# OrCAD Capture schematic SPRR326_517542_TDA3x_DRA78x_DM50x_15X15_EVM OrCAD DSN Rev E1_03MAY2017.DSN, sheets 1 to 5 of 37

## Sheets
1 SH01 - TITLE PAGE: title: TDA3x/DRA78x/DM50x - 15X15 EVM; rev: E1; company: TEXAS INSTRUMENTS INCORPORATED; note: 517542; note: TI CONFIDENTIAL - NDA RESTRICTIONS; note: Preliminary Information - Subject to change
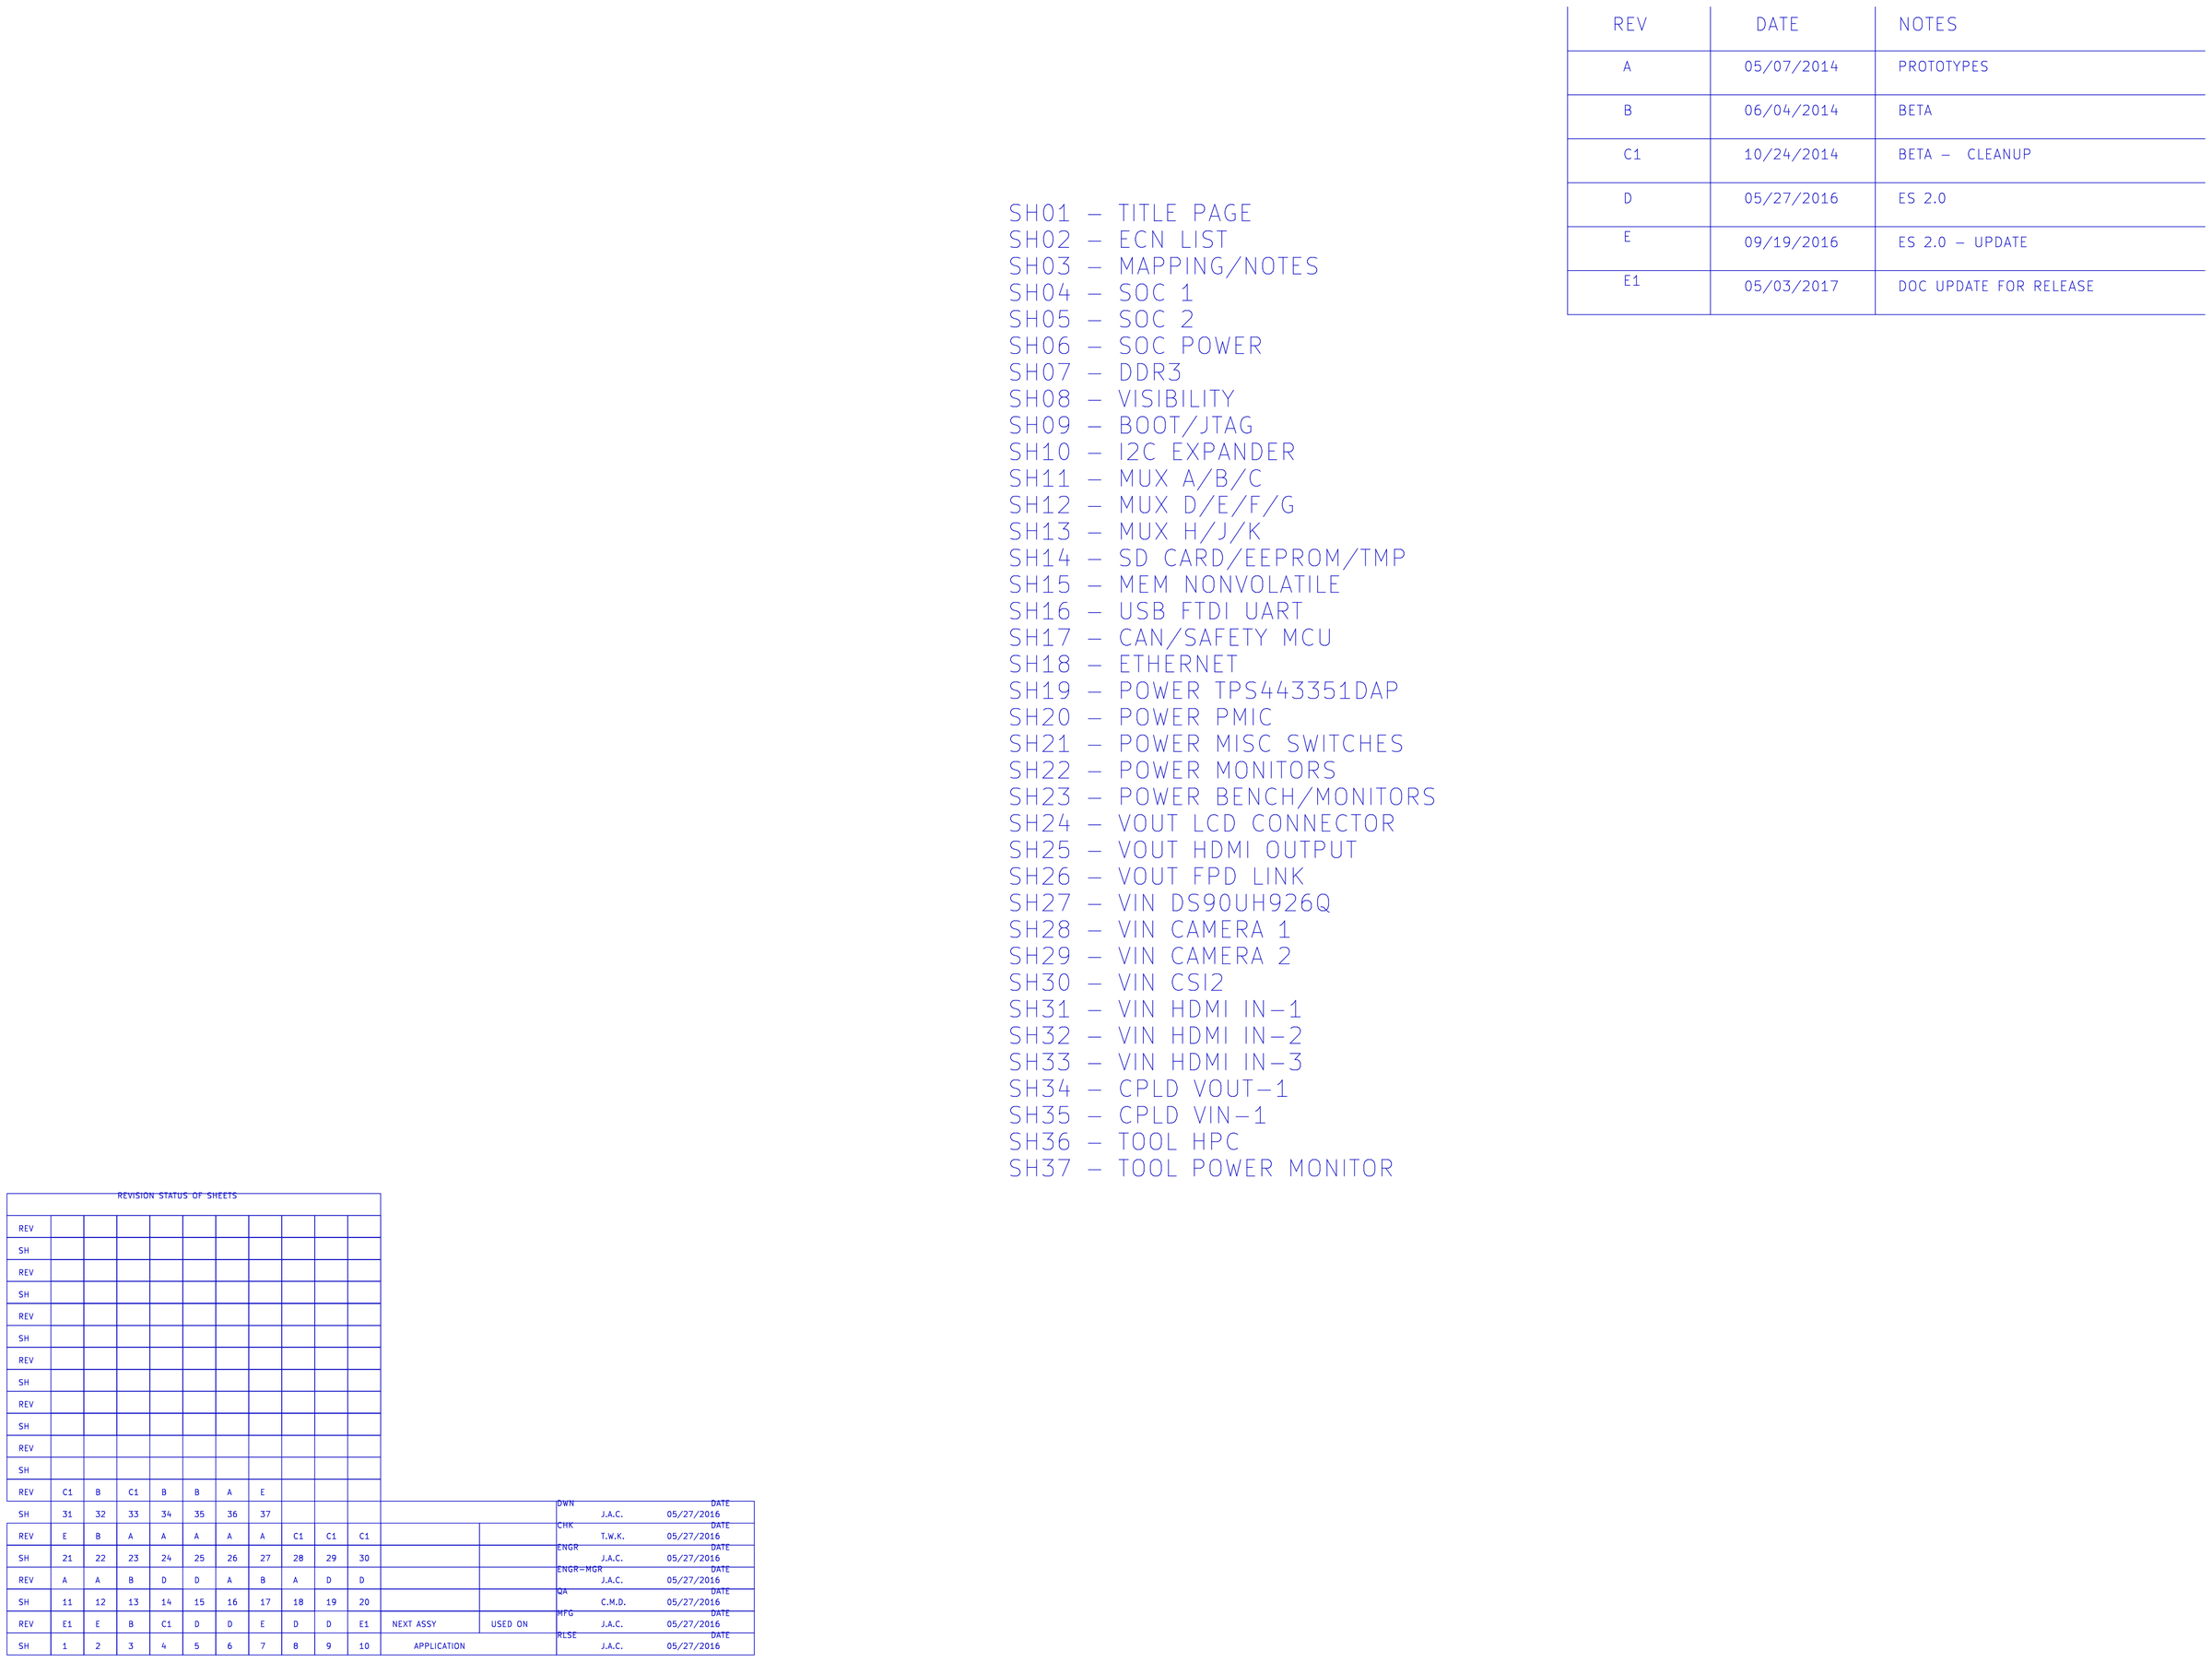
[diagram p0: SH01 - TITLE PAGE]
2 SH02 - ECN LIST: rev: E
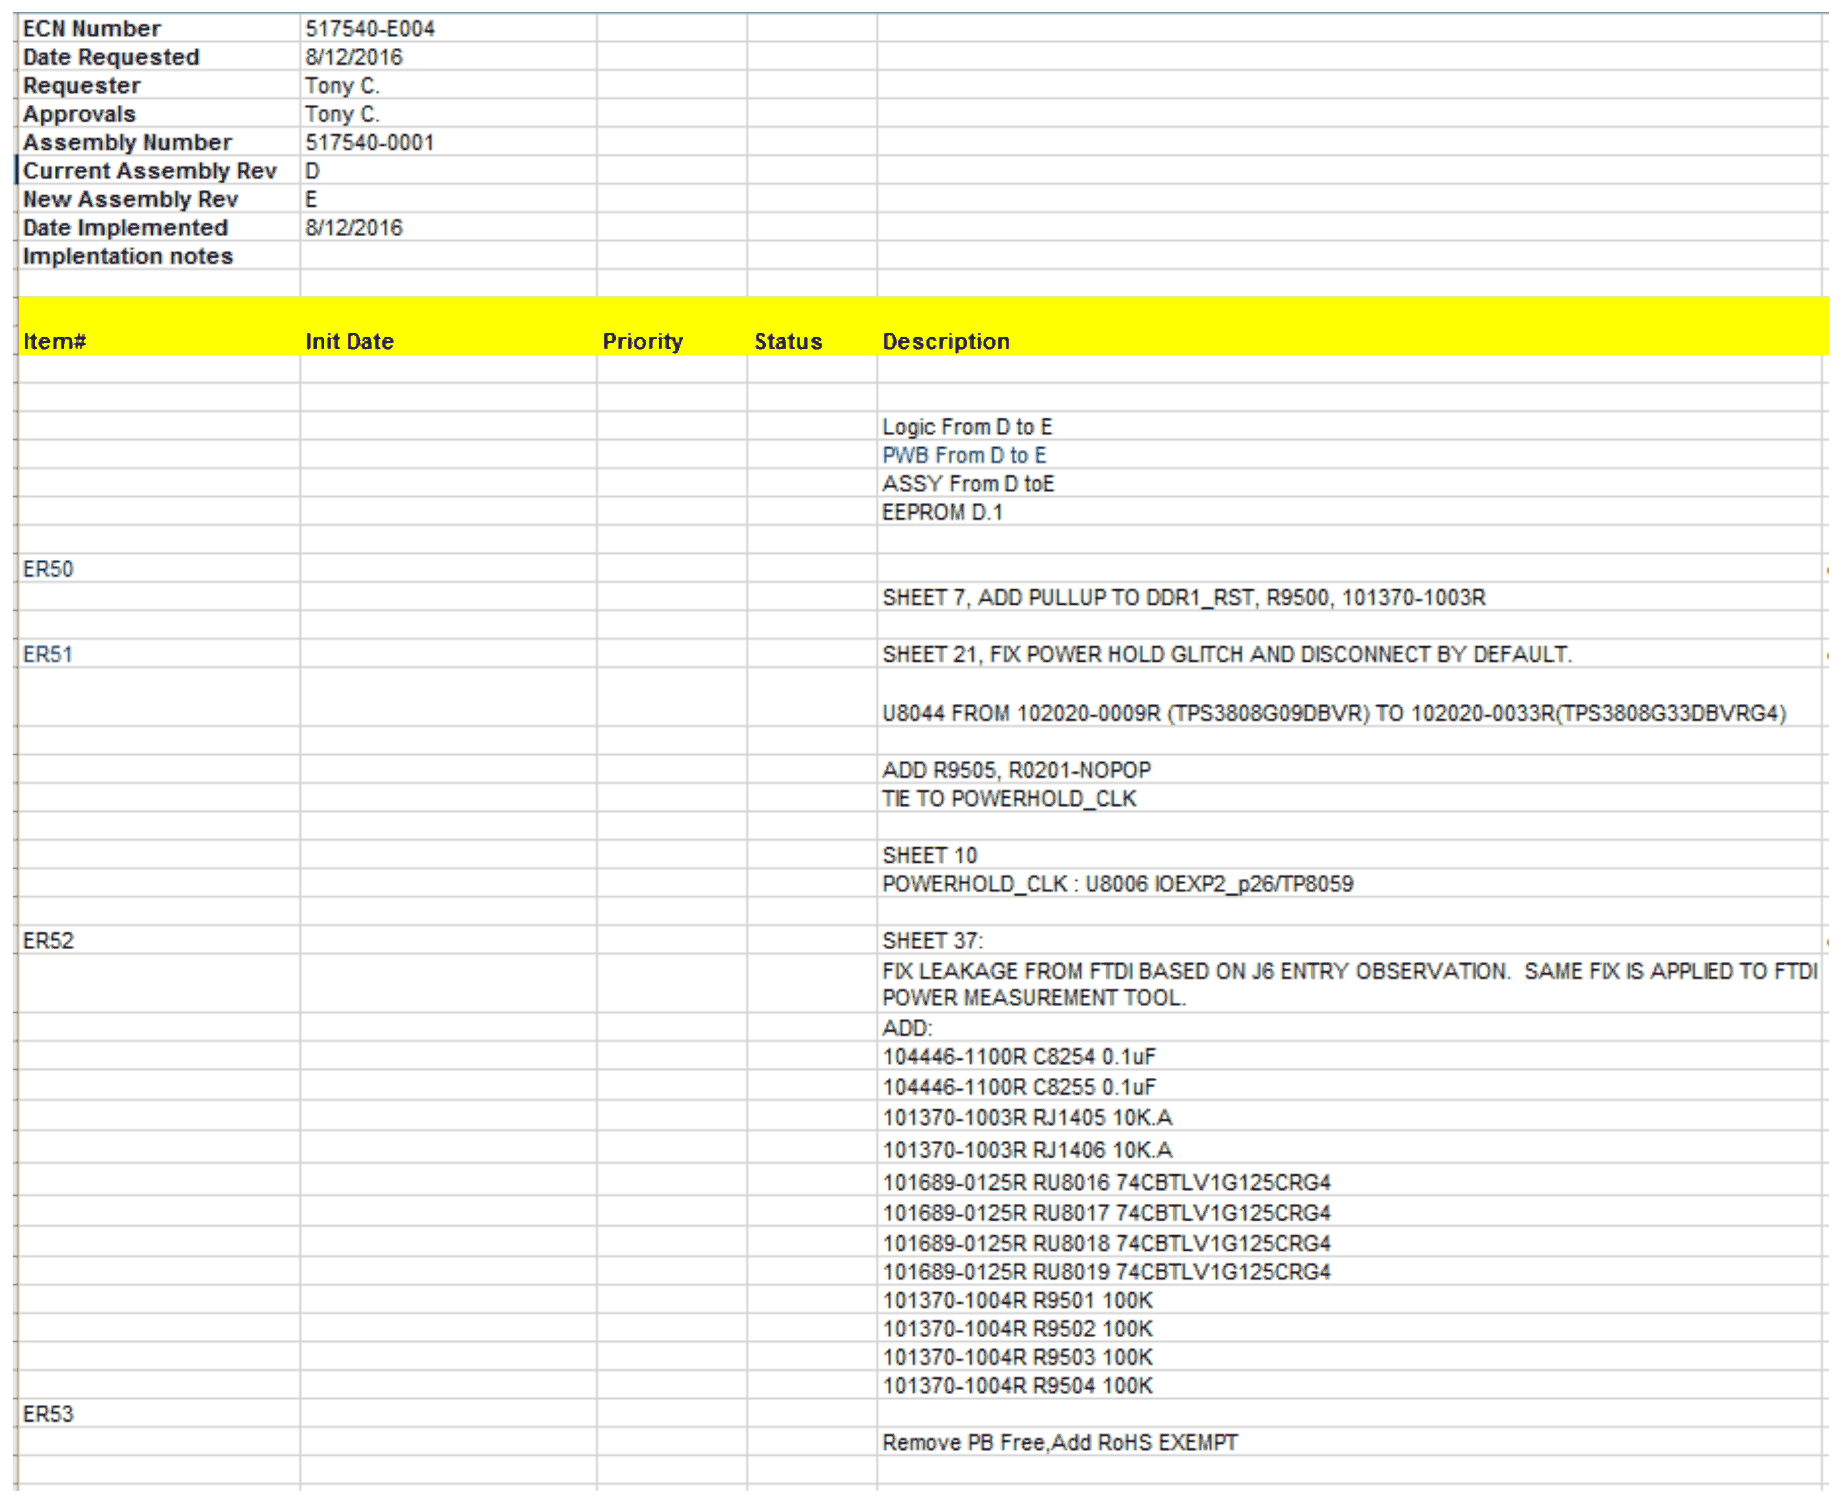
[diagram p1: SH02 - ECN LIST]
3 SH04 - SOC 1: size C; rev: C1
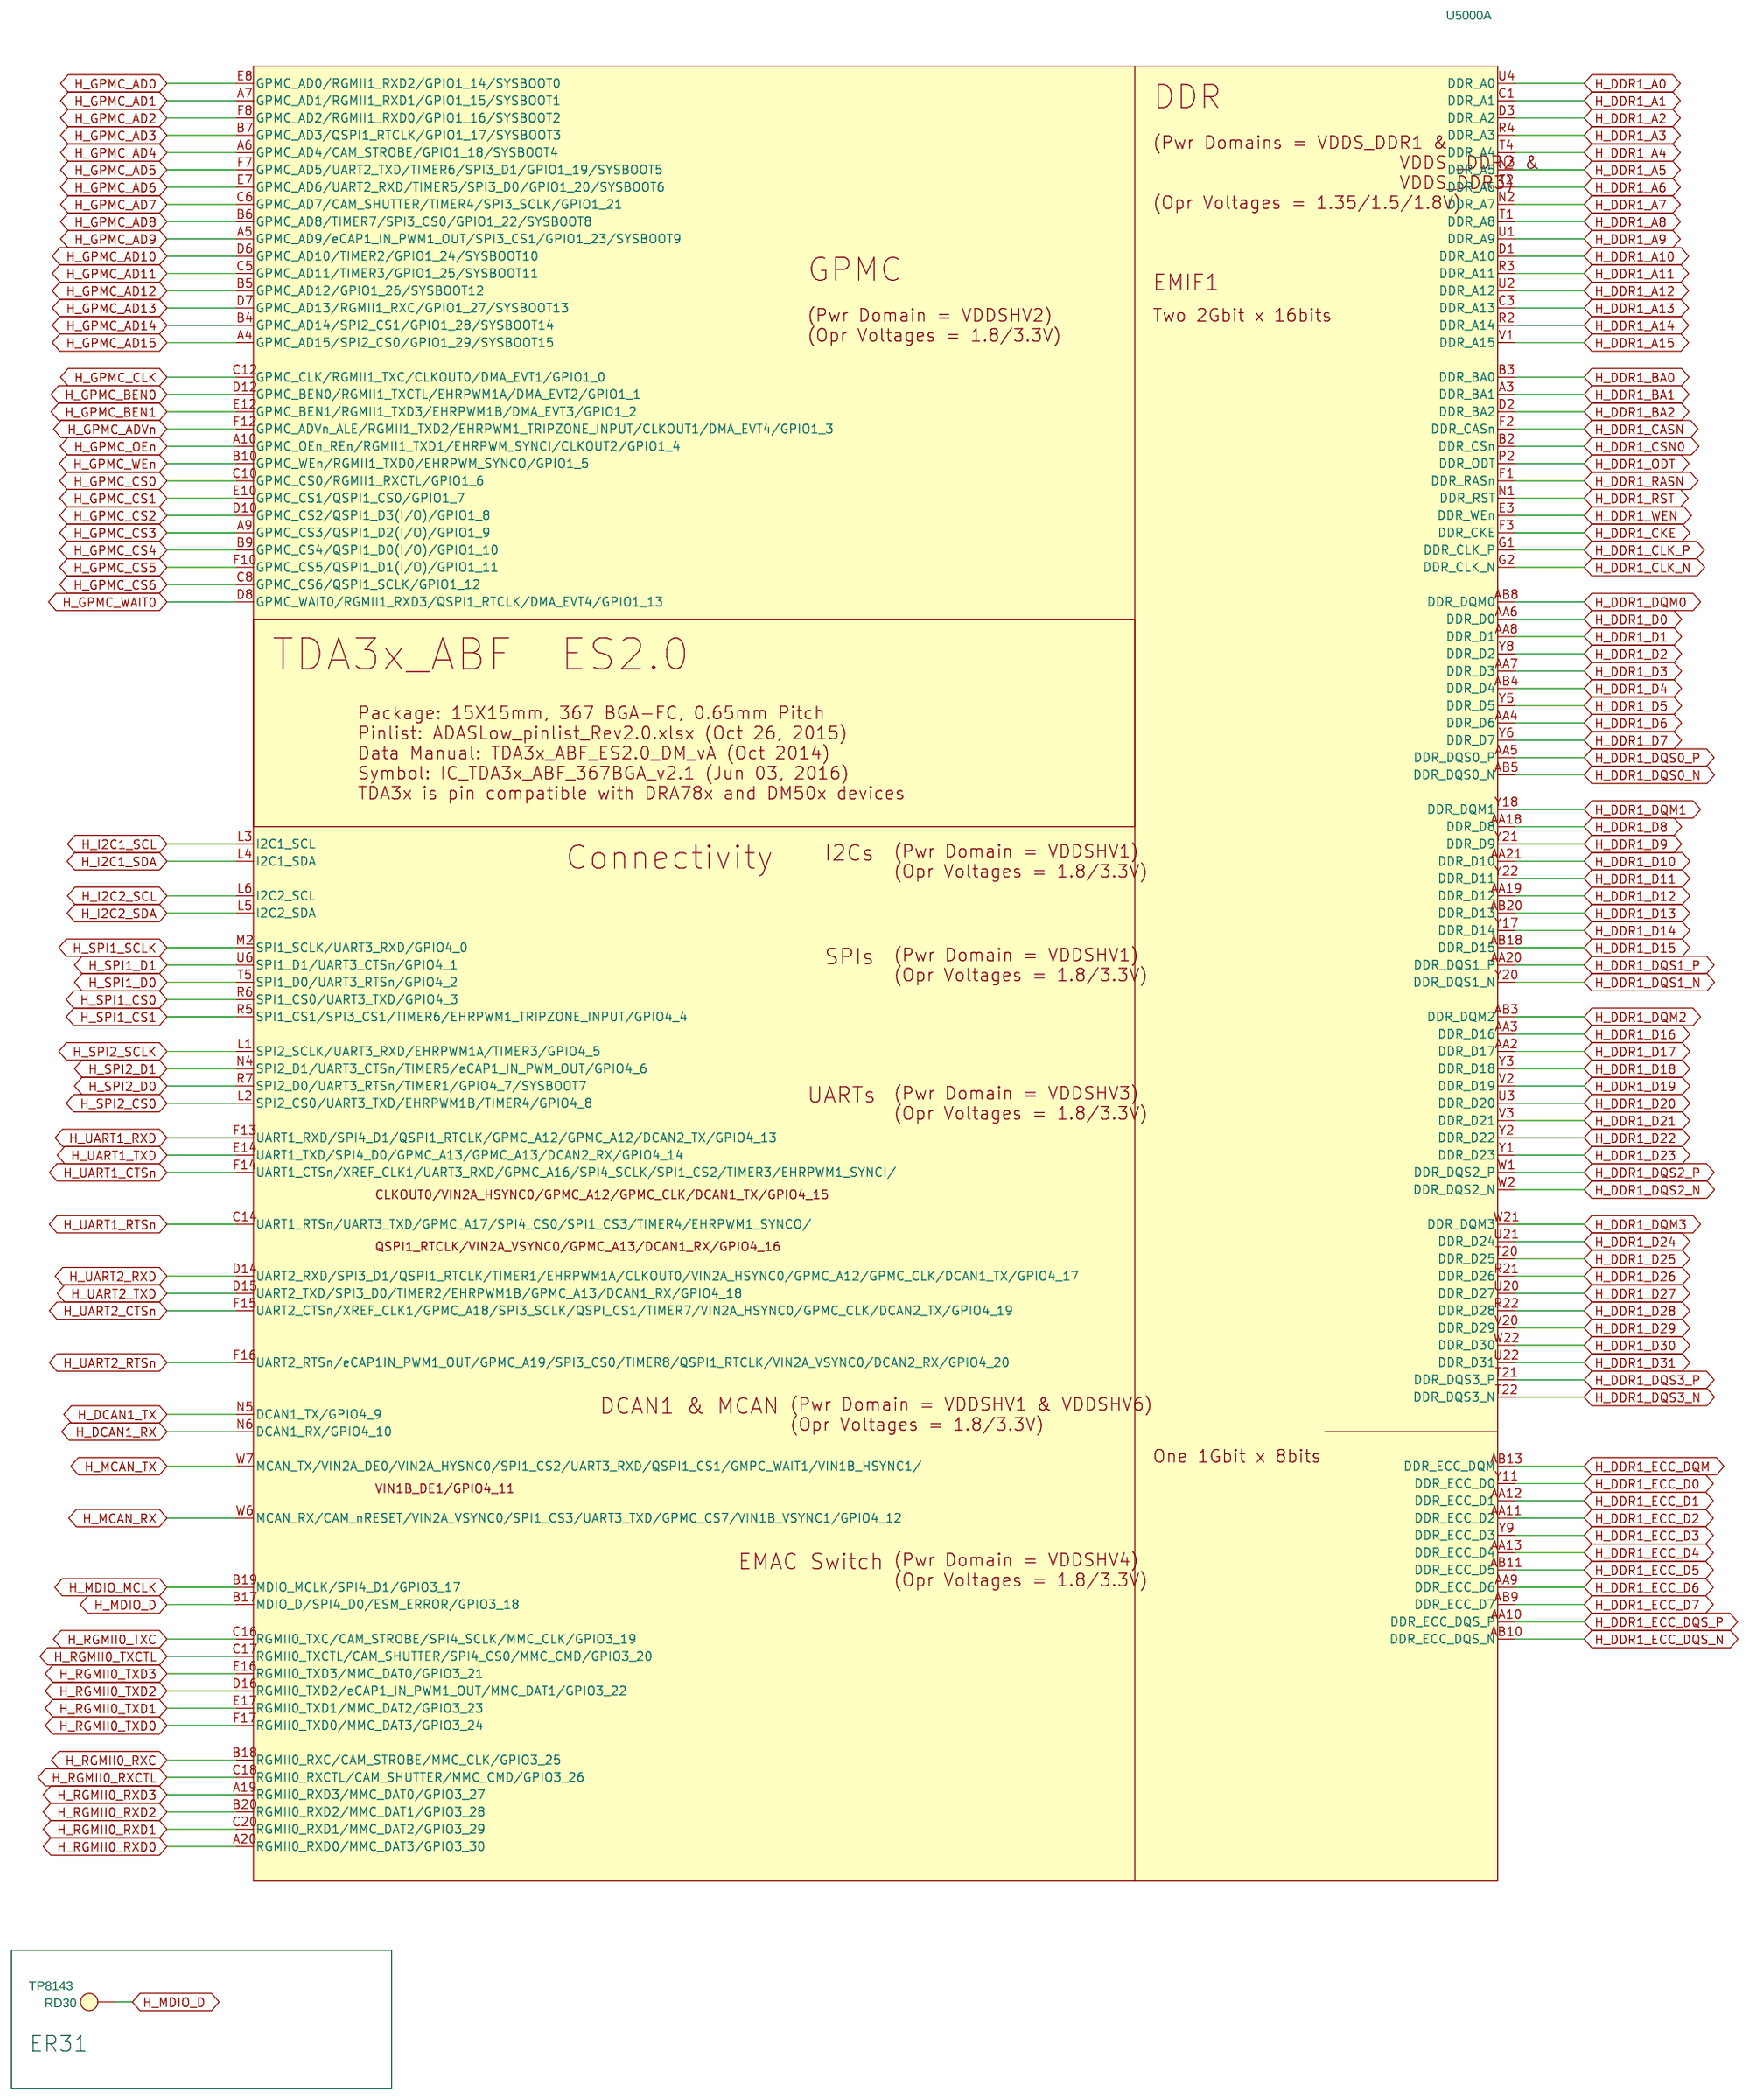
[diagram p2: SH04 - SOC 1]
4 SH05 - SOC 2: size C; rev: D
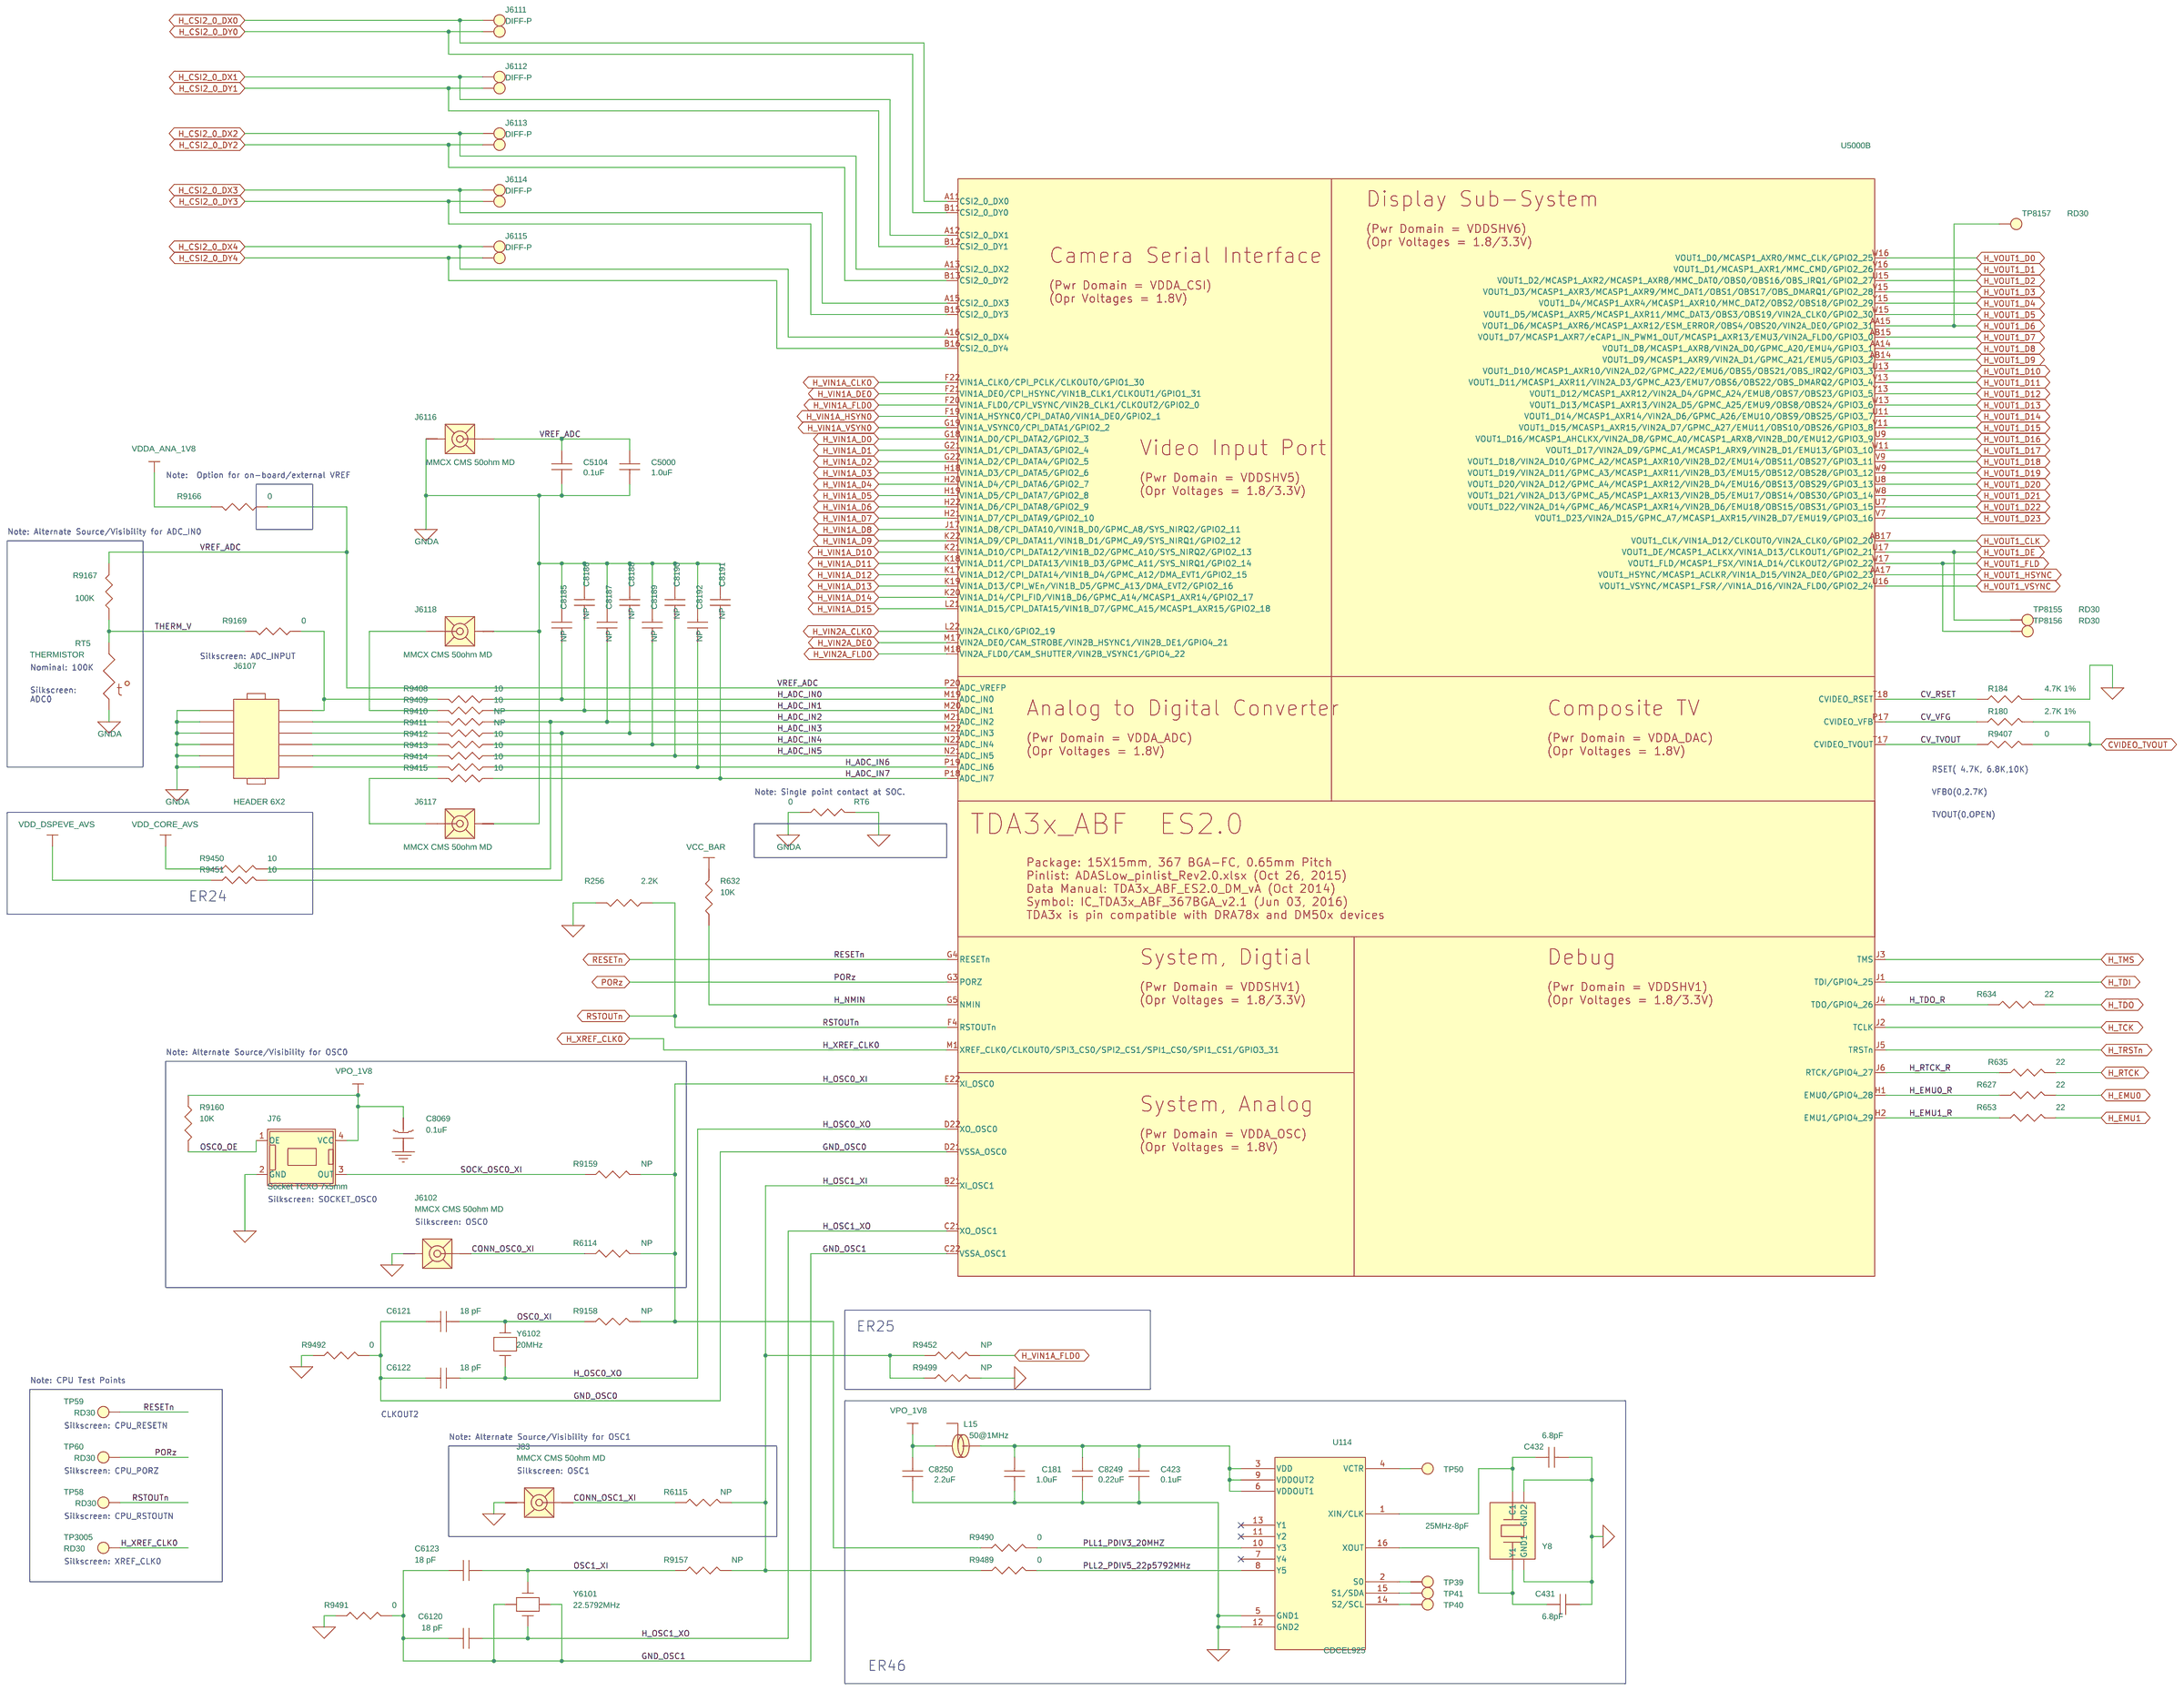
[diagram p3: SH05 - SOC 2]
5 SH06 - SOC POWER: size C; rev: D
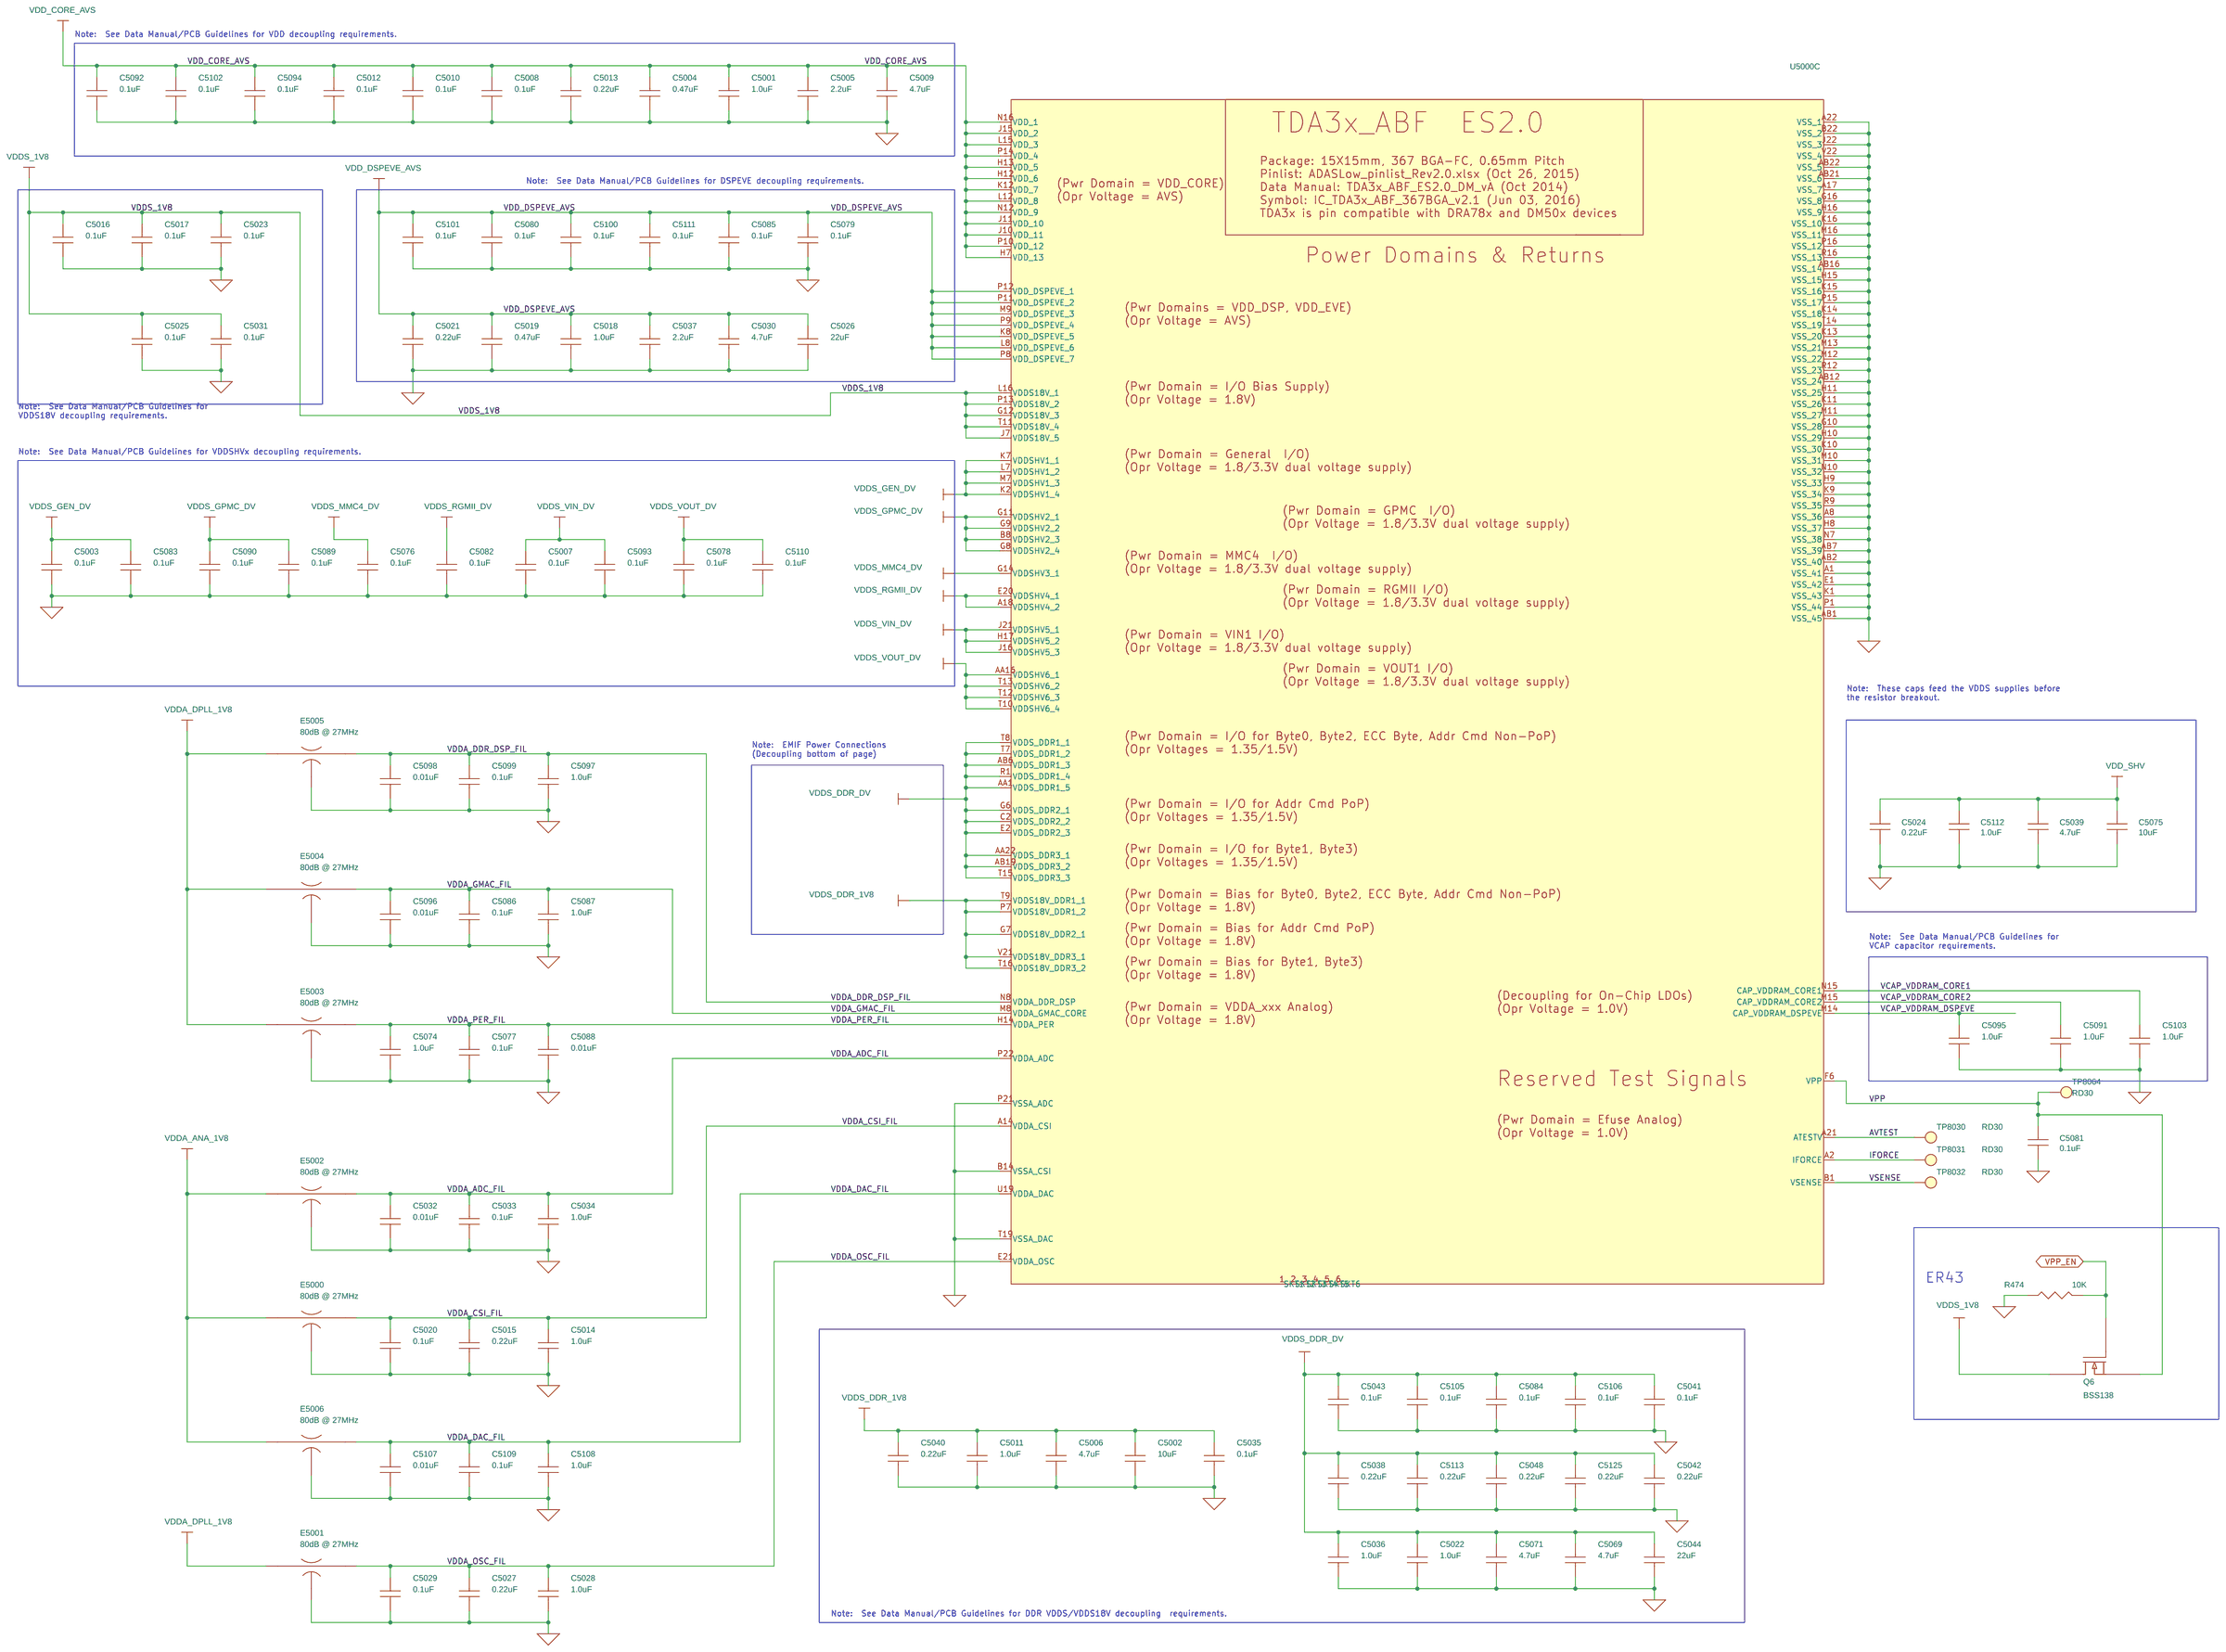
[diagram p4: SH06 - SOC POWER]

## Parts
sheet SH04 - SOC 1
TP8143  RD30  [tp-30RD13]
U5000  TDA3x_ABF, 15X15, 0.65mm, 367 BGA  [sktbga-22x22-13349]  (sections A,B,C)
sheet SH05 - SOC 2
C181  1.0uF  [c603-35x45]
C423  0.1uF  [c402-25]
C431  6.8pF  [c402-25]
C432  6.8pF  [c402-25]
C5000  1.0uF  [c603-35x45]
C5104  0.1uF  [c402-25rd]
C6120  18 pF  [c402-25]
C6121  18 pF  [c402-25]
C6122  18 pF  [c402-25]
C6123  18 pF  [c402-25]
C8069  0.1uF  [c402-25]
C8185  NP  [c402-25rd]
C8186  NP  [c402-25rd]
C8187  NP  [c402-25rd]
C8188  NP  [c402-25rd]
C8189  NP  [c402-25rd]
C8190  NP  [c402-25rd]
C8191  NP  [c402-25rd]
C8192  NP  [c402-25rd]
C8249  0.22uF  [c603-35x45]
C8250  2.2uF  [c603-35x45]
J76  Socket TCXO 7x5mm  [X-T_CXP-A04_01]
J83  MMCX CMS 50ohm MD  [ti-jms_mcx_01]
J6102  MMCX CMS 50ohm MD  [ti-jms_mcx_01]
J6107  HEADER 6X2  [JUMP2X6-6040]
J6111  DIFF-P  [diff0402-30d13]
J6112  DIFF-P  [diff0402-30d13]
J6113  DIFF-P  [diff0402-30d13]
J6114  DIFF-P  [diff0402-30d13]
J6115  DIFF-P  [diff0402-30d13]
J6116  MMCX CMS 50ohm MD  [ti-jms_mcx_01]
J6117  MMCX CMS 50ohm MD  [ti-jms_mcx_01]
J6118  MMCX CMS 50ohm MD  [ti-jms_mcx_01]
L15  50@1MHz  [l603-35x45]
R180  2.7K 1%  [r402-25]
R184  4.7K 1%  [r402-25]
R256  2.2K  [r402-25]
R627  22  [r402-25]
R632  10K  [r402-25]
R634  22  [r402-25]
R635  22  [r402-25]
R653  22  [r402-25]
R6114  NP  [r402-25]
R6115  NP  [r402-25]
R9157  NP  [r201-6p6spc]
R9158  NP  [r201-6p6spc]
R9159  NP  [r402-25]
R9160  10K  [r402-25]
R9166  0  [r402-25]
R9167  100K  [r402-25]
R9169  0  [r402-25]
R9407  0  [r402-25]
R9408  10  [r402-25]
R9409  10  [r402-25]
R9410  NP  [r402-25]
R9411  NP  [r402-25]
R9412  10  [r402-25]
R9413  10  [r402-25]
R9414  10  [r402-25]
R9415  10  [r402-25]
R9450  10  [r402-25]
R9451  10  [r402-25]
R9452  NP  [r201-6p6spc]
R9489  0  [r201-6p6spc]
R9490  0  [r201-6p6spc]
R9491  0  [r201-6p6spc]
R9492  0  [r201-6p6spc]
R9499  NP  [r201-6p6spc]
RT5  THERMISTOR  [r603-35X45]
RT6  0  [r201-6p6spc]
TP39  TP  [TP20]
TP40  TP  [TP20]
TP41  TP  [TP20]
TP50  TP  [TP20]
TP58  RD30  [tp-30RD13]
TP59  RD30  [tp-30RD13]
TP60  RD30  [tp-30RD13]
TP3005  RD30  [tp-30RD13]
TP8155  RD30  [tp-30RD13]
TP8156  RD30  [tp-30RD13]
TP8157  RD30  [tp-30RD13]
U114  CDCEL925  [pw16-14x70]
Y8  25MHz-8pF  [xtal4-32x35-abm10]
Y6101  22.5792MHz  [xtal4-55x87]
Y6102  20MHz  [xtal2-75x94]
sheet SH06 - SOC POWER
C5001  1.0uF  [c603-35x45]
C5002  10uF  [c805-35x60]
C5003  0.1uF  [c402-25rd]
C5004  0.47uF  [c603-35x45]
C5005  2.2uF  [c603-35x45]
C5006  4.7uF  [c805-35x60]
C5007  0.1uF  [c402-25rd]
C5008  0.1uF  [c402-25rd]
C5009  4.7uF  [c805-35x60]
C5010  0.1uF  [c402-25rd]
C5011  1.0uF  [c603-35x45]
C5012  0.1uF  [c402-25rd]
C5013  0.22uF  [c603-35x45]
C5014  1.0uF  [c603-35x45]
C5015  0.22uF  [c603-35x45]
C5016  0.1uF  [c402-25rd]
C5017  0.1uF  [c402-25rd]
C5018  1.0uF  [c603-35x45]
C5019  0.47uF  [c603-35x45]
C5020  0.1uF  [c402-25rd]
C5021  0.22uF  [c603-35x45]
C5022  1.0uF  [c603-35x45]
C5023  0.1uF  [c402-25rd]
C5024  0.22uF  [c603-35x45]
C5025  0.1uF  [c402-25rd]
C5026  22uF  [c1206-40x70]
C5027  0.22uF  [c603-35x45]
C5028  1.0uF  [c603-35x45]
C5029  0.1uF  [c402-25rd]
C5030  4.7uF  [c805-35x60]
C5031  0.1uF  [c402-25rd]
C5032  0.01uF  [c402-25rd]
C5033  0.1uF  [c402-25rd]
C5034  1.0uF  [c603-35x45]
C5035  0.1uF  [c402-25rd]
C5036  1.0uF  [c603-35x45]
C5037  2.2uF  [c603-35x45]
C5038  0.22uF  [c603-35x45]
C5039  4.7uF  [c805-35x60]
C5040  0.22uF  [c603-35x45]
C5041  0.1uF  [c402-25rd]
C5042  0.22uF  [c603-35x45]
C5043  0.1uF  [c402-25rd]
C5044  22uF  [c1206-40x70]
C5048  0.22uF  [c603-35x45]
C5069  4.7uF  [c805-35x60]
C5071  4.7uF  [c805-35x60]
C5074  1.0uF  [c603-35x45]
C5075  10uF  [c805-35x60]
C5076  0.1uF  [c402-25rd]
C5077  0.1uF  [c402-25rd]
C5078  0.1uF  [c402-25rd]
C5079  0.1uF  [c402-25rd]
C5080  0.1uF  [c402-25rd]
C5081  0.1uF  [c402-25rd]
C5082  0.1uF  [c402-25rd]
C5083  0.1uF  [c402-25rd]
C5084  0.1uF  [c402-25rd]
C5085  0.1uF  [c402-25rd]
C5086  0.1uF  [c402-25rd]
C5087  1.0uF  [c603-35x45]
C5088  0.01uF  [c402-25rd]
C5089  0.1uF  [c402-25rd]
C5090  0.1uF  [c402-25rd]
C5091  1.0uF  [c603-35x45]
C5092  0.1uF  [c402-25rd]
C5093  0.1uF  [c402-25rd]
C5094  0.1uF  [c402-25rd]
C5095  1.0uF  [c603-35x45]
C5096  0.01uF  [c402-25rd]
C5097  1.0uF  [c603-35x45]
C5098  0.01uF  [c402-25rd]
C5099  0.1uF  [c402-25rd]
C5100  0.1uF  [c402-25rd]
C5101  0.1uF  [c402-25rd]
C5102  0.1uF  [c402-25rd]
C5103  1.0uF  [c603-35x45]
C5105  0.1uF  [c402-25rd]
C5106  0.1uF  [c402-25rd]
C5107  0.01uF  [c402-25rd]
C5108  1.0uF  [c603-35x45]
C5109  0.1uF  [c402-25rd]
C5110  0.1uF  [c402-25rd]
C5111  0.1uF  [c402-25rd]
C5112  1.0uF  [c603-35x45]
C5113  0.22uF  [c603-35x45]
C5125  0.22uF  [c603-35x45]
E5000  80dB @ 27MHz  [EMI-NFM21P]
E5001  80dB @ 27MHz  [EMI-NFM21P]
E5002  80dB @ 27MHz  [EMI-NFM21P]
E5003  80dB @ 27MHz  [EMI-NFM21P]
E5004  80dB @ 27MHz  [EMI-NFM21P]
E5005  80dB @ 27MHz  [EMI-NFM21P]
E5006  80dB @ 27MHz  [EMI-NFM21P]
Q6  BSS138  [SOT23-28X44-GSD]
R474  10K  [r402-25]
TP8030  RD30  [tp-30RD13]
TP8031  RD30  [tp-30RD13]
TP8032  RD30  [tp-30RD13]
TP8064  RD30  [tp-30RD13]

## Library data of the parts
TP58-TP60 TP3005 TP8030-TP8032 TP8064 TP8143 TP8155-TP8157 = TESTPOINT: Part #: TP-30RD13-NO-POP
U5000 = IC_TDA3x_ABF_367BGA_v2_0.0: Part #: 104471-0001R-TI
C181 = CAP_AM_0603_1.0uf_x7r_16v_10_X: Part #: 104723-0100R
C423 C5003 C5007 C5008 C5010 C5012 C5016 C5017 C5020 C5023 C5025 C5029 C5031 C5033 C5035 C5076-C5086 C5089 C5090 C5092-C5094 C5099-C5102 C5104-C5106 C5109-C5111 = CAP_AM_0402_0.1uf_x7r_16v_10%_X: Part #: 104446-1100R
C431 C432 = CAP_NP_3: Part #: 102366-1685R
C5000 C5001 C5011 C5014 C5018 C5022 C5028 C5034 C5036 C5074 C5087 C5091 C5095 C5097 C5103 C5108 C5112 = CAP_AM_0603_1.0uf_x7r_16v_10_X: Part #: 103497-0100R
C6120-C6123 = CAP_NP_3: Part #: 101782-1184R
C8069 = CAP: Part #: 104446-1100R
C8185-C8192 = CAP_AM_0402_0.1uf_x7r_16v_10%_X: Part #: C0402-NOPOP
C8249 = CAP_AM_0603_2.2uf_x7r_6.3v_10_X: Part #: 103885-1220R
C5005 C5037 C8250 = CAP_AM_0603_2.2uf_x7r_6.3v_10_X: Part #: 104448-0220R
J76 = CXP-A04-21-00_SOCKET_TCXO: Part #: 104465-0001R
J83 J6102 J6116-J6118 = MMCX_SM1_50_MD: Part #: 104457-0001R
J6107 = HEADER_6X2: Part #: 100116-0006R
J6111-J6115 = HEADER_2_1: Part #: NO-POP
L15 = FERRITE_CHIP_0: Part #: 101858-2201R
R180 = R_0: Part #: 102145-2702R
R184 = R: Part #: 102145-4702R
R256 = R: Part #: 101370-2202R
R627 R634 R635 R653 = R: Part #: 101370-2200R
R474 R632 R9160 = R: Part #: 101370-1003R
R6114 R6115 R9159 R9410 R9411 = R: Part #: R0402-NOPOP
R9157 R9158 R9452 R9499 = R: Part #: R0201-NOPOP
R9166 R9169 = R_1: Part #: 101370-0001R
R9167 = R_1: Part #: 101370-1004R
R9407 = R_0: Part #: 101370-0001R
R9408 R9409 R9412-R9415 R9450 R9451 = R: Part #: 101370-1000R
R9489-R9492 = R: Part #: 103158-0001R
RT5 = THERMISTOR: Part #: 103719-1004R
RT6 = R_1: Part #: 103158-0001R
TP39-TP41 TP50 = TESTPOINT: Part #: NO-POP
U114 = CDCE925: Part #: 104758-0001R-TI
Y8 = CRYSTAL_4-PIN_0: Part #: 103419-0250R
Y6101 = CRYSTAL_22.5792MHz: Part #: 102740-0225R
Y6102 = CRYSTAL_0: Part #: 101590-0200R
C5002 C5075 = CAP_AM_0805_10uf_x7r_10v_10_X: Part #: 104447-0101R
C5004 C5019 = CAP_AM_0603_0.47uf_x7r_16v_10_X: Part #: 103816-1470R
C5006 C5009 C5030 C5039 C5069 C5071 = CAP_AM_0805_4.7uf_x7r_16v_10_X: Part #: 101063-0470R
C5013 C5015 C5021 C5024 C5027 C5038 C5040 C5042 C5048 C5113 C5125 = CAP_AM_0603_0.22uf_x8l_16v_10_X: Part #: 103885-1220R
C5026 C5044 = CAP_AM_1206_22uf_x7r_6.3v_20_X: Part #: 104463-0221R
C5032 C5088 C5096 C5098 C5107 = CAP_AM_0402_0.01uf_x7r_25v_10_X: Part #: 101587-1101R
C5041 C5043 = CAP_AM_0603_0.22uf_x8l_16v_10_X: Part #: 104446-1100R
E5000-E5006 = EMIFIL_0805_0.47uF_2A_80dB27M_X: Part #: 102569-1470R
Q6 = MOSFET_N_1: Part #: 100680-0001R

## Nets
GND: C181.2 C423.2 C431.2 C432.2 C5001.2 C5002.2 C5003.2 C5004.2 C5005.2 C5006.2 C5007.2 C5008.2 C5009.2 C5010.2 C5011.2 C5012.2 C5013.2 C5014.2 C5015.2 C5016.2 C5017.2 C5018.2 C5019.2 C5020.2 C5021.2 C5022.2 C5023.2 C5024.2 C5025.2 C5026.2 C5027.2 C5028.2 C5029.2 C5030.2 C5031.2 C5032.2 C5033.2 C5034.2 C5035.2 C5036.2 C5037.2 C5038.2 C5039.2 C5040.2 C5041.2 C5042.2 C5043.2 C5044.2 C5048.2 C5069.2 C5071.2 C5074.2 C5075.2 C5076.2 C5077.2 C5078.2 C5079.2 C5080.2 C5081.2 C5082.2 C5083.2 C5084.2 C5085.2 C5086.2 C5087.2 C5088.2 C5089.2 C5090.2 C5091.2 C5092.2 C5093.2 C5094.2 C5095.2 C5096.2 C5097.2 C5098.2 C5099.2 C5100.2 C5101.2 C5102.2 C5103.2 C5105.2 C5106.2 C5107.2 C5108.2 C5109.2 C5110.2 C5111.2 C5112.2 C5113.2 C5125.2 C8069.1 C8249.2 C8250.2 E5000.2 E5001.2 E5002.2 E5003.2 E5004.2 E5005.2 E5006.2 J76.2(GND) J83.2 J83.3 J83.4 J83.5 J6102.2 J6102.3 J6102.4 J6102.5 R184.2 R256.2 R474.1 R9491.1 R9492.1 R9499.2 RT6.1 U114.5(GND1) U114.12(GND2) U5000.A1(VSS_41) U5000.A8(VSS_36) U5000.A17(VSS_7) U5000.A22(VSS_1) U5000.AB1(VSS_45) U5000.AB2(VSS_40) U5000.AB7(VSS_39) U5000.AB12(VSS_24) U5000.AB16(VSS_14) U5000.AB21(VSS_6) U5000.AB22(VSS_5) U5000.B14(VSSA_CSI) U5000.B22(VSS_2) U5000.E1(VSS_42) U5000.G10(VSS_28) U5000.G16(VSS_8) U5000.H8(VSS_37) U5000.H9(VSS_33) U5000.H10(VSS_29) U5000.H11(VSS_25) U5000.H15(VSS_15) U5000.H16(VSS_9) U5000.J22(VSS_3) U5000.K1(VSS_43) U5000.K9(VSS_34) U5000.K10(VSS_30) U5000.K11(VSS_26) U5000.K13(VSS_20) U5000.K14(VSS_18) U5000.K15(VSS_16) U5000.K16(VSS_10) U5000.M10(VSS_31) U5000.M11(VSS_27) U5000.M12(VSS_22) U5000.M13(VSS_21) U5000.M16(VSS_11) U5000.N7(VSS_38) U5000.N10(VSS_32) U5000.P1(VSS_44) U5000.P15(VSS_17) U5000.P16(VSS_12) U5000.P21(VSSA_ADC) U5000.R9(VSS_35) U5000.R12(VSS_23) U5000.R16(VSS_13) U5000.T14(VSS_19) U5000.T19(VSSA_DAC) U5000.V22(VSS_4) Y8.2(GND1) Y8.4(GND2) ; also on sheet 6 7 8 9 10 11 12 13 14 15 16 17 18 19 20 21 22 23 25 26 27 28 29 30 31 32 34 35 36 37
GND_OSC0: C6121.2 C6122.2 R9492.2 U5000.D21(VSSA_OSC0)
GND_OSC1: C6120.2 C6123.2 R9491.2 U5000.C22(VSSA_OSC1) Y6101.2 Y6101.4
GNDA: C5000.2 C5104.2 C8185.1 C8186.1 C8187.1 C8188.1 C8189.1 C8190.1 C8191.1 C8192.1 J6107.2 J6107.4 J6107.6 J6107.8 J6107.10 J6107.12 J6116.2 J6116.3 J6116.4 J6116.5 J6117.2 J6117.3 J6117.4 J6117.5 J6118.2 J6118.3 J6118.4 J6118.5 RT5.2 RT6.2
VDD_CORE_AVS: C5001.1 C5004.1 C5005.1 C5008.1 C5009.1 C5010.1 C5012.1 C5013.1 C5092.1 C5094.1 C5102.1 R9450.1 U5000.H7(VDD_13) U5000.H12(VDD_6) U5000.H13(VDD_5) U5000.J10(VDD_11) U5000.J11(VDD_10) U5000.J15(VDD_2) U5000.K12(VDD_7) U5000.L12(VDD_8) U5000.L15(VDD_3) U5000.N12(VDD_9) U5000.N16(VDD_1) U5000.P10(VDD_12) U5000.P14(VDD_4) ; also on sheet 37
VDD_DSPEVE_AVS: C5018.1 C5019.1 C5021.1 C5026.1 C5030.1 C5037.1 C5079.1 C5080.1 C5085.1 C5100.1 C5101.1 C5111.1 R9451.1 U5000.K8(VDD_DSPEVE_5) U5000.L8(VDD_DSPEVE_6) U5000.M9(VDD_DSPEVE_3) U5000.P8(VDD_DSPEVE_7) U5000.P9(VDD_DSPEVE_4) U5000.P11(VDD_DSPEVE_2) U5000.P12(VDD_DSPEVE_1) ; also on sheet 37
VDD_SHV: C5024.1 C5039.1 C5075.1 C5112.1 ; also on sheet 7 15
VDDA_ADC_FIL: C5032.1 C5033.1 C5034.1 E5002.3 U5000.P22(VDDA_ADC)
VDDA_ANA_1V8: E5000.1 E5002.1 E5006.1 R9166.1 ; also on sheet 15
VDDA_CSI_FIL: C5014.1 C5015.1 C5020.1 E5000.3 U5000.A14(VDDA_CSI)
VDDA_DAC_FIL: C5107.1 C5108.1 C5109.1 E5006.3 U5000.U19(VDDA_DAC)
VDDA_DDR_DSP_FIL: C5097.1 C5098.1 C5099.1 E5005.3 U5000.N8(VDDA_DDR_DSP)
VDDA_DPLL_1V8: E5001.1 E5003.1 E5004.1 E5005.1 ; also on sheet 15
VDDA_GMAC_FIL: C5086.1 C5087.1 C5096.1 E5004.3 U5000.M8(VDDA_GMAC_CORE)
VDDA_OSC_FIL: C5027.1 C5028.1 C5029.1 E5001.3 U5000.E21(VDDA_OSC)
VDDA_PER_FIL: C5074.1 C5077.1 C5088.1 E5003.3 U5000.H14(VDDA_PER)
VDDS_1V8: C5016.1 C5017.1 C5023.1 C5025.1 C5031.1 Q6.D U5000.G12(VDDS18V_3) U5000.J7(VDDS18V_5) U5000.L16(VDDS18V_1) U5000.P13(VDDS18V_2) U5000.T11(VDDS18V_4) ; also on sheet 15
VDDS_DDR_1V8: C5002.1 C5006.1 C5011.1 C5035.1 C5040.1 U5000.G7(VDDS18V_DDR2_1) U5000.P7(VDDS18V_DDR1_2) U5000.T9(VDDS18V_DDR1_1) U5000.T16(VDDS18V_DDR3_2) U5000.V21(VDDS18V_DDR3_1) ; also on sheet 15
VDDS_DDR_DV: C5022.1 C5036.1 C5038.1 C5041.1 C5042.1 C5043.1 C5044.1 C5048.1 C5069.1 C5071.1 C5084.1 C5105.1 C5106.1 C5113.1 C5125.1 U5000.AA1(VDDS_DDR1_5) U5000.AA22(VDDS_DDR3_1) U5000.AB6(VDDS_DDR1_3) U5000.AB19(VDDS_DDR3_2) U5000.C2(VDDS_DDR2_2) U5000.E2(VDDS_DDR2_3) U5000.G6(VDDS_DDR2_1) U5000.R1(VDDS_DDR1_4) U5000.T7(VDDS_DDR1_2) U5000.T8(VDDS_DDR1_1) U5000.T15(VDDS_DDR3_3) ; also on sheet 37
VDDS_GEN_DV: C5003.1 C5083.1 U5000.K2(VDDSHV1_4) U5000.K7(VDDSHV1_1) U5000.L7(VDDSHV1_2) U5000.M7(VDDSHV1_3) ; also on sheet 15
VDDS_GPMC_DV: C5089.1 C5090.1 U5000.B8(VDDSHV2_3) U5000.G8(VDDSHV2_4) U5000.G9(VDDSHV2_2) U5000.G11(VDDSHV2_1) ; also on sheet 15
VDDS_MMC4_DV: C5076.1 U5000.G14(VDDSHV3_1) ; also on sheet 15
VDDS_RGMII_DV: C5082.1 U5000.A18(VDDSHV4_2) U5000.E20(VDDSHV4_1) ; also on sheet 15
VDDS_VIN_DV: C5007.1 C5093.1 U5000.H17(VDDSHV5_2) U5000.J16(VDDSHV5_3) U5000.J21(VDDSHV5_1) ; also on sheet 15
VDDS_VOUT_DV: C5078.1 C5110.1 U5000.AA16(VDDSHV6_1) U5000.T10(VDDSHV6_4) U5000.T12(VDDSHV6_3) U5000.T13(VDDSHV6_2) ; also on sheet 15
AVTEST: TP8030.1(TP) U5000.A21(ATESTV)
CONN_OSC0_XI: J6102.1(CENTER) R6114.1
CONN_OSC1_XI: J83.1(CENTER) R6115.1
CV_RSET: R184.1 U5000.T18(CVIDEO_RSET)
CV_TVOUT: R9407.1 U5000.T17(CVIDEO_TVOUT)
CV_VFG: R180.1 U5000.P17(CVIDEO_VFB)
CVIDEO_TVOUT: R180.2 R9407.2 ; also on sheet 16
H_ADC_IN0: C8185.2 R9408.1 U5000.M19(ADC_IN0)
H_ADC_IN1: C8186.2 R9409.1 U5000.M20(ADC_IN1)
H_ADC_IN2: C8187.2 R9410.1 R9450.2 U5000.M21(ADC_IN2)
H_ADC_IN3: C8188.2 R9411.1 R9451.2 U5000.M22(ADC_IN3)
H_ADC_IN4: C8189.2 R9412.1 U5000.N22(ADC_IN4)
H_ADC_IN5: C8190.2 R9413.1 U5000.N21(ADC_IN5)
H_ADC_IN6: C8192.2 R9414.1 U5000.P19(ADC_IN6)
H_ADC_IN7: C8191.2 R9415.1 U5000.P18(ADC_IN7)
H_CSI2_0_DX0: J6111.1 U5000.A11(CSI2_0_DX0) ; also on sheet 22
H_CSI2_0_DX1: J6112.1 U5000.A12(CSI2_0_DX1) ; also on sheet 22
H_CSI2_0_DX2: J6113.1 U5000.A13(CSI2_0_DX2) ; also on sheet 22
H_CSI2_0_DX3: J6114.1 U5000.A15(CSI2_0_DX3) ; also on sheet 22
H_CSI2_0_DX4: J6115.1 U5000.A16(CSI2_0_DX4) ; also on sheet 22
H_CSI2_0_DY0: J6111.2 U5000.B11(CSI2_0_DY0) ; also on sheet 22
H_CSI2_0_DY1: J6112.2 U5000.B12(CSI2_0_DY1) ; also on sheet 22
H_CSI2_0_DY2: J6113.2 U5000.B13(CSI2_0_DY2) ; also on sheet 22
H_CSI2_0_DY3: J6114.2 U5000.B15(CSI2_0_DY3) ; also on sheet 22
H_CSI2_0_DY4: J6115.2 U5000.B16(CSI2_0_DY4) ; also on sheet 22
H_DCAN1_RX: U5000.N6(DCAN1_RX/GPIO4_10) ; also on sheet 7
H_DCAN1_TX: U5000.N5(DCAN1_TX/GPIO4_9) ; also on sheet 7
H_DDR1_A0: U5000.U4(DDR_A0) ; also on sheet 6
H_DDR1_A1: U5000.C1(DDR_A1) ; also on sheet 6
H_DDR1_A2: U5000.D3(DDR_A2) ; also on sheet 6
H_DDR1_A3: U5000.R4(DDR_A3) ; also on sheet 6
H_DDR1_A4: U5000.T4(DDR_A4) ; also on sheet 6
H_DDR1_A5: U5000.N3(DDR_A5) ; also on sheet 6
H_DDR1_A6: U5000.T2(DDR_A6) ; also on sheet 6
H_DDR1_A7: U5000.N2(DDR_A7) ; also on sheet 6
H_DDR1_A8: U5000.T1(DDR_A8) ; also on sheet 6
H_DDR1_A9: U5000.U1(DDR_A9) ; also on sheet 6
H_DDR1_A10: U5000.D1(DDR_A10) ; also on sheet 6
H_DDR1_A11: U5000.R3(DDR_A11) ; also on sheet 6
H_DDR1_A12: U5000.U2(DDR_A12) ; also on sheet 6
H_DDR1_A13: U5000.C3(DDR_A13) ; also on sheet 6
H_DDR1_A14: U5000.R2(DDR_A14) ; also on sheet 6
H_DDR1_A15: U5000.V1(DDR_A15) ; also on sheet 6
H_DDR1_BA0: U5000.B3(DDR_BA0) ; also on sheet 6
H_DDR1_BA1: U5000.A3(DDR_BA1) ; also on sheet 6
H_DDR1_BA2: U5000.D2(DDR_BA2) ; also on sheet 6
H_DDR1_CASN: U5000.F2(DDR_CASn) ; also on sheet 6
H_DDR1_CKE: U5000.F3(DDR_CKE) ; also on sheet 6
H_DDR1_CLK_N: U5000.G2(DDR_CLK_N) ; also on sheet 6
H_DDR1_CLK_P: U5000.G1(DDR_CLK_P) ; also on sheet 6
H_DDR1_CSN0: U5000.B2(DDR_CSn) ; also on sheet 6
H_DDR1_D0: U5000.AA6(DDR_D0) ; also on sheet 6
H_DDR1_D1: U5000.AA8(DDR_D1) ; also on sheet 6
H_DDR1_D2: U5000.Y8(DDR_D2) ; also on sheet 6
H_DDR1_D3: U5000.AA7(DDR_D3) ; also on sheet 6
H_DDR1_D4: U5000.AB4(DDR_D4) ; also on sheet 6
H_DDR1_D5: U5000.Y5(DDR_D5) ; also on sheet 6
H_DDR1_D6: U5000.AA4(DDR_D6) ; also on sheet 6
H_DDR1_D7: U5000.Y6(DDR_D7) ; also on sheet 6
H_DDR1_D8: U5000.AA18(DDR_D8) ; also on sheet 6
H_DDR1_D9: U5000.Y21(DDR_D9) ; also on sheet 6
H_DDR1_D10: U5000.AA21(DDR_D10) ; also on sheet 6
H_DDR1_D11: U5000.Y22(DDR_D11) ; also on sheet 6
H_DDR1_D12: U5000.AA19(DDR_D12) ; also on sheet 6
H_DDR1_D13: U5000.AB20(DDR_D13) ; also on sheet 6
H_DDR1_D14: U5000.Y17(DDR_D14) ; also on sheet 6
H_DDR1_D15: U5000.AB18(DDR_D15) ; also on sheet 6
H_DDR1_D16: U5000.AA3(DDR_D16) ; also on sheet 6
H_DDR1_D17: U5000.AA2(DDR_D17) ; also on sheet 6
H_DDR1_D18: U5000.Y3(DDR_D18) ; also on sheet 6
H_DDR1_D19: U5000.V2(DDR_D19) ; also on sheet 6
H_DDR1_D20: U5000.U3(DDR_D20) ; also on sheet 6
H_DDR1_D21: U5000.V3(DDR_D21) ; also on sheet 6
H_DDR1_D22: U5000.Y2(DDR_D22) ; also on sheet 6
H_DDR1_D23: U5000.Y1(DDR_D23) ; also on sheet 6
H_DDR1_D24: U5000.U21(DDR_D24) ; also on sheet 6
H_DDR1_D25: U5000.T20(DDR_D25) ; also on sheet 6
H_DDR1_D26: U5000.R21(DDR_D26) ; also on sheet 6
H_DDR1_D27: U5000.U20(DDR_D27) ; also on sheet 6
H_DDR1_D28: U5000.R22(DDR_D28) ; also on sheet 6
H_DDR1_D29: U5000.V20(DDR_D29) ; also on sheet 6
H_DDR1_D30: U5000.W22(DDR_D30) ; also on sheet 6
H_DDR1_D31: U5000.U22(DDR_D31) ; also on sheet 6
H_DDR1_DQM0: U5000.AB8(DDR_DQM0) ; also on sheet 6
H_DDR1_DQM1: U5000.Y18(DDR_DQM1) ; also on sheet 6
H_DDR1_DQM2: U5000.AB3(DDR_DQM2) ; also on sheet 6
H_DDR1_DQM3: U5000.W21(DDR_DQM3) ; also on sheet 6
H_DDR1_DQS0_N: U5000.AB5(DDR_DQS0_N) ; also on sheet 6
H_DDR1_DQS0_P: U5000.AA5(DDR_DQS0_P) ; also on sheet 6
H_DDR1_DQS1_N: U5000.Y20(DDR_DQS1_N) ; also on sheet 6
H_DDR1_DQS1_P: U5000.AA20(DDR_DQS1_P) ; also on sheet 6
H_DDR1_DQS2_N: U5000.W2(DDR_DQS2_N) ; also on sheet 6
H_DDR1_DQS2_P: U5000.W1(DDR_DQS2_P) ; also on sheet 6
H_DDR1_DQS3_N: U5000.T22(DDR_DQS3_N) ; also on sheet 6
H_DDR1_DQS3_P: U5000.T21(DDR_DQS3_P) ; also on sheet 6
H_DDR1_ECC_D0: U5000.Y11(DDR_ECC_D0) ; also on sheet 6
H_DDR1_ECC_D1: U5000.AA12(DDR_ECC_D1) ; also on sheet 6
H_DDR1_ECC_D2: U5000.AA11(DDR_ECC_D2) ; also on sheet 6
H_DDR1_ECC_D3: U5000.Y9(DDR_ECC_D3) ; also on sheet 6
H_DDR1_ECC_D4: U5000.AA13(DDR_ECC_D4) ; also on sheet 6
H_DDR1_ECC_D5: U5000.AB11(DDR_ECC_D5) ; also on sheet 6
H_DDR1_ECC_D6: U5000.AA9(DDR_ECC_D6) ; also on sheet 6
H_DDR1_ECC_D7: U5000.AB9(DDR_ECC_D7) ; also on sheet 6
H_DDR1_ECC_DQM: U5000.AB13(DDR_ECC_DQM) ; also on sheet 6
H_DDR1_ECC_DQS_N: U5000.AB10(DDR_ECC_DQS_N) ; also on sheet 6
H_DDR1_ECC_DQS_P: U5000.AA10(DDR_ECC_DQS_P) ; also on sheet 6
H_DDR1_ODT: U5000.P2(DDR_ODT) ; also on sheet 6
H_DDR1_RASN: U5000.F1(DDR_RASn) ; also on sheet 6
H_DDR1_RST: U5000.N1(DDR_RST) ; also on sheet 6
H_DDR1_WEN: U5000.E3(DDR_WEn) ; also on sheet 6
H_EMU0: R627.2 ; also on sheet 31
H_EMU0_R: R627.1 U5000.H1(EMU0/GPIO4_28)
H_EMU1: R653.2 ; also on sheet 31
H_EMU1_R: R653.1 U5000.H2(EMU1/GPIO4_29)
H_GPMC_AD0: U5000.E8(GPMC_AD0/RGMII1_RXD2/GPIO1_14/SYSBOOT0) ; also on sheet 7
H_GPMC_AD1: U5000.A7(GPMC_AD1/RGMII1_RXD1/GPIO1_15/SYSBOOT1) ; also on sheet 7
H_GPMC_AD2: U5000.F8(GPMC_AD2/RGMII1_RXD0/GPIO1_16/SYSBOOT2) ; also on sheet 7
H_GPMC_AD3: U5000.B7(GPMC_AD3/QSPI1_RTCLK/GPIO1_17/SYSBOOT3) ; also on sheet 7
H_GPMC_AD4: U5000.A6(GPMC_AD4/CAM_STROBE/GPIO1_18/SYSBOOT4) ; also on sheet 7
H_GPMC_AD5: U5000.F7(GPMC_AD5/UART2_TXD/TIMER6/SPI3_D1/GPIO1_19/SYSBOOT5) ; also on sheet 7
H_GPMC_AD6: U5000.E7(GPMC_AD6/UART2_RXD/TIMER5/SPI3_D0/GPIO1_20/SYSBOOT6) ; also on sheet 7
H_GPMC_AD7: U5000.C6(GPMC_AD7/CAM_SHUTTER/TIMER4/SPI3_SCLK/GPIO1_21) ; also on sheet 7
H_GPMC_AD8: U5000.B6(GPMC_AD8/TIMER7/SPI3_CS0/GPIO1_22/SYSBOOT8) ; also on sheet 7
H_GPMC_AD9: U5000.A5(GPMC_AD9/eCAP1_IN_PWM1_OUT/SPI3_CS1/GPIO1_23/SYSBOOT9) ; also on sheet 7
H_GPMC_AD10: U5000.D6(GPMC_AD10/TIMER2/GPIO1_24/SYSBOOT10) ; also on sheet 7
H_GPMC_AD11: U5000.C5(GPMC_AD11/TIMER3/GPIO1_25/SYSBOOT11) ; also on sheet 7
H_GPMC_AD12: U5000.B5(GPMC_AD12/GPIO1_26/SYSBOOT12) ; also on sheet 7
H_GPMC_AD13: U5000.D7(GPMC_AD13/RGMII1_RXC/GPIO1_27/SYSBOOT13) ; also on sheet 7
H_GPMC_AD14: U5000.B4(GPMC_AD14/SPI2_CS1/GPIO1_28/SYSBOOT14) ; also on sheet 7
H_GPMC_AD15: U5000.A4(GPMC_AD15/SPI2_CS0/GPIO1_29/SYSBOOT15) ; also on sheet 7
H_GPMC_ADVn: U5000.F12(GPMC_ADVn_ALE/RGMII1_TXD2/EHRPWM1_TRIPZONE_INPUT/CLKOUT1/DMA_EVT4/GPIO1_3) ; also on sheet 7
H_GPMC_BEN0: U5000.D12(GPMC_BEN0/RGMII1_TXCTL/EHRPWM1A/DMA_EVT2/GPIO1_1) ; also on sheet 7
H_GPMC_BEN1: U5000.E12(GPMC_BEN1/RGMII1_TXD3/EHRPWM1B/DMA_EVT3/GPIO1_2) ; also on sheet 7
H_GPMC_CLK: U5000.C12(GPMC_CLK/RGMII1_TXC/CLKOUT0/DMA_EVT1/GPIO1_0) ; also on sheet 7
H_GPMC_CS0: U5000.C10(GPMC_CS0/RGMII1_RXCTL/GPIO1_6) ; also on sheet 7
H_GPMC_CS1: U5000.E10(GPMC_CS1/QSPI1_CS0/GPIO1_7) ; also on sheet 7
H_GPMC_CS2: U5000.D10(GPMC_CS2/QSPI1_D3(I/O)/GPIO1_8) ; also on sheet 7
H_GPMC_CS3: U5000.A9(GPMC_CS3/QSPI1_D2(I/O)/GPIO1_9) ; also on sheet 7
H_GPMC_CS4: U5000.B9(GPMC_CS4/QSPI1_D0(I/O)/GPIO1_10) ; also on sheet 7
H_GPMC_CS5: U5000.F10(GPMC_CS5/QSPI1_D1(I/O)/GPIO1_11) ; also on sheet 7
H_GPMC_CS6: U5000.C8(GPMC_CS6/QSPI1_SCLK/GPIO1_12) ; also on sheet 7
H_GPMC_OEn: U5000.A10(GPMC_OEn_REn/RGMII1_TXD1/EHRPWM_SYNCI/CLKOUT2/GPIO1_4) ; also on sheet 7
H_GPMC_WAIT0: U5000.D8(GPMC_WAIT0/RGMII1_RXD3/QSPI1_RTCLK/DMA_EVT4/GPIO1_13) ; also on sheet 7
H_GPMC_WEn: U5000.B10(GPMC_WEn/RGMII1_TXD0/EHRPWM_SYNCO/GPIO1_5) ; also on sheet 7
H_I2C1_SCL: U5000.L3(I2C1_SCL) ; also on sheet 7
H_I2C1_SDA: U5000.L4(I2C1_SDA) ; also on sheet 7
H_I2C2_SCL: U5000.L6(I2C2_SCL) ; also on sheet 7
H_I2C2_SDA: U5000.L5(I2C2_SDA) ; also on sheet 7
H_MCAN_RX: U5000.W6(MCAN_RX/CAM_nRESET/VIN2A_VSYNC0/SPI1_CS3/UART3_TXD/GPMC_CS7/VIN1B_VSYNC1/GPIO4_12) ; also on sheet 7
H_MCAN_TX: U5000.W7(MCAN_TX/VIN2A_DE0/VIN2A_HYSNC0/SPI1_CS2/UART3_RXD/QSPI1_CS1/GMPC_WAIT1/VIN1B_HSYNC1/) ; also on sheet 7
H_MDIO_D: TP8143.1(TP) U5000.B17(MDIO_D/SPI4_D0/ESM_ERROR/GPIO3_18) ; also on sheet 7
H_MDIO_MCLK: U5000.B19(MDIO_MCLK/SPI4_D1/GPIO3_17) ; also on sheet 7
H_NMIN: R632.2 U5000.G5(NMIN)
H_OSC0_XI: R6114.2 R9158.2 R9159.2 R9490.1 U5000.E22(XI_OSC0)
H_OSC0_XO: C6122.1 U5000.D22(XO_OSC0) Y6102.1
H_OSC1_XI: R6115.2 R9157.2 R9452.1 R9489.1 R9499.1 U5000.B21(XI_OSC1)
H_OSC1_XO: C6120.1 U5000.C21(XO_OSC1) Y6101.1
H_RGMII0_RXC: U5000.B18(RGMII0_RXC/CAM_STROBE/MMC_CLK/GPIO3_25) ; also on sheet 7
H_RGMII0_RXCTL: U5000.C18(RGMII0_RXCTL/CAM_SHUTTER/MMC_CMD/GPIO3_26) ; also on sheet 7
H_RGMII0_RXD0: U5000.A20(RGMII0_RXD0/MMC_DAT3/GPIO3_30) ; also on sheet 7
H_RGMII0_RXD1: U5000.C20(RGMII0_RXD1/MMC_DAT2/GPIO3_29) ; also on sheet 7
H_RGMII0_RXD2: U5000.B20(RGMII0_RXD2/MMC_DAT1/GPIO3_28) ; also on sheet 7
H_RGMII0_RXD3: U5000.A19(RGMII0_RXD3/MMC_DAT0/GPIO3_27) ; also on sheet 7
H_RGMII0_TXC: U5000.C16(RGMII0_TXC/CAM_STROBE/SPI4_SCLK/MMC_CLK/GPIO3_19) ; also on sheet 7
H_RGMII0_TXCTL: U5000.C17(RGMII0_TXCTL/CAM_SHUTTER/SPI4_CS0/MMC_CMD/GPIO3_20) ; also on sheet 7
H_RGMII0_TXD0: U5000.F17(RGMII0_TXD0/MMC_DAT3/GPIO3_24) ; also on sheet 7
H_RGMII0_TXD1: U5000.E17(RGMII0_TXD1/MMC_DAT2/GPIO3_23) ; also on sheet 7
H_RGMII0_TXD2: U5000.D16(RGMII0_TXD2/eCAP1_IN_PWM1_OUT/MMC_DAT1/GPIO3_22) ; also on sheet 7
H_RGMII0_TXD3: U5000.E16(RGMII0_TXD3/MMC_DAT0/GPIO3_21) ; also on sheet 7
H_RTCK: R635.2 ; also on sheet 31
H_RTCK_R: R635.1 U5000.J6(RTCK/GPIO4_27)
H_SPI1_CS0: U5000.R6(SPI1_CS0/UART3_TXD/GPIO4_3) ; also on sheet 7
H_SPI1_CS1: U5000.R5(SPI1_CS1/SPI3_CS1/TIMER6/EHRPWM1_TRIPZONE_INPUT/GPIO4_4) ; also on sheet 7
H_SPI1_D0: U5000.T5(SPI1_D0/UART3_RTSn/GPIO4_2) ; also on sheet 7
H_SPI1_D1: U5000.U6(SPI1_D1/UART3_CTSn/GPIO4_1) ; also on sheet 7
H_SPI1_SCLK: U5000.M2(SPI1_SCLK/UART3_RXD/GPIO4_0) ; also on sheet 7
H_SPI2_CS0: U5000.L2(SPI2_CS0/UART3_TXD/EHRPWM1B/TIMER4/GPIO4_8) ; also on sheet 7
H_SPI2_D0: U5000.R7(SPI2_D0/UART3_RTSn/TIMER1/GPIO4_7/SYSBOOT7) ; also on sheet 7
H_SPI2_D1: U5000.N4(SPI2_D1/UART3_CTSn/TIMER5/eCAP1_IN_PWM_OUT/GPIO4_6) ; also on sheet 7
H_SPI2_SCLK: U5000.L1(SPI2_SCLK/UART3_RXD/EHRPWM1A/TIMER3/GPIO4_5) ; also on sheet 7
H_TCK: U5000.J2(TCLK) ; also on sheet 31
H_TDI: U5000.J1(TDI/GPIO4_25) ; also on sheet 31
H_TDO: R634.2 ; also on sheet 31
H_TDO_R: R634.1 U5000.J4(TDO/GPIO4_26)
H_TMS: U5000.J3(TMS) ; also on sheet 31
H_TRSTn: U5000.J5(TRSTn) ; also on sheet 31
H_UART1_CTSn: U5000.F14(UART1_CTSn/XREF_CLK1/UART3_RXD/GPMC_A16/SPI4_SCLK/SPI1_CS2/TIMER3/EHRPWM1_SYNCI/) ; also on sheet 7
H_UART1_RTSn: U5000.C14(UART1_RTSn/UART3_TXD/GPMC_A17/SPI4_CS0/SPI1_CS3/TIMER4/EHRPWM1_SYNCO/) ; also on sheet 7
H_UART1_RXD: U5000.F13(UART1_RXD/SPI4_D1/QSPI1_RTCLK/GPMC_A12/GPMC_A12/DCAN2_TX/GPIO4_13) ; also on sheet 7
H_UART1_TXD: U5000.E14(UART1_TXD/SPI4_D0/GPMC_A13/GPMC_A13/DCAN2_RX/GPIO4_14) ; also on sheet 7
H_UART2_CTSn: U5000.F15(UART2_CTSn/XREF_CLK1/GPMC_A18/SPI3_SCLK/QSPI_CS1/TIMER7/VIN2A_HSYNC0/GPMC_CLK/DCAN2_TX/GPIO4_19) ; also on sheet 7
H_UART2_RTSn: U5000.F16(UART2_RTSn/eCAP1IN_PWM1_OUT/GPMC_A19/SPI3_CS0/TIMER8/QSPI1_RTCLK/VIN2A_VSYNC0/DCAN2_RX/GPIO4_20) ; also on sheet 7
H_UART2_RXD: U5000.D14(UART2_RXD/SPI3_D1/QSPI1_RTCLK/TIMER1/EHRPWM1A/CLKOUT0/VIN2A_HSYNC0/GPMC_A12/GPMC_CLK/DCAN1_TX/GPIO4_17) ; also on sheet 7
H_UART2_TXD: U5000.D15(UART2_TXD/SPI3_D0/TIMER2/EHRPWM1B/GPMC_A13/DCAN1_RX/GPIO4_18) ; also on sheet 7
H_VIN1A_CLK0: U5000.F22(VIN1A_CLK0/CPI_PCLK/CLKOUT0/GPIO1_30) ; also on sheet 7
H_VIN1A_D0: U5000.G18(VIN1A_D0/CPI_DATA2/GPIO2_3) ; also on sheet 7
H_VIN1A_D1: U5000.G21(VIN1A_D1/CPI_DATA3/GPIO2_4) ; also on sheet 7
H_VIN1A_D2: U5000.G22(VIN1A_D2/CPI_DATA4/GPIO2_5) ; also on sheet 7
H_VIN1A_D3: U5000.H18(VIN1A_D3/CPI_DATA5/GPIO2_6) ; also on sheet 7
H_VIN1A_D4: U5000.H20(VIN1A_D4/CPI_DATA6/GPIO2_7) ; also on sheet 7
H_VIN1A_D5: U5000.H19(VIN1A_D5/CPI_DATA7/GPIO2_8) ; also on sheet 7
H_VIN1A_D6: U5000.H22(VIN1A_D6/CPI_DATA8/GPIO2_9) ; also on sheet 7
H_VIN1A_D7: U5000.H21(VIN1A_D7/CPI_DATA9/GPIO2_10) ; also on sheet 7
H_VIN1A_D8: U5000.J17(VIN1A_D8/CPI_DATA10/VIN1B_D0/GPMC_A8/SYS_NIRQ2/GPIO2_11) ; also on sheet 7
H_VIN1A_D9: U5000.K22(VIN1A_D9/CPI_DATA11/VIN1B_D1/GPMC_A9/SYS_NIRQ1/GPIO2_12) ; also on sheet 7
H_VIN1A_D10: U5000.K21(VIN1A_D10/CPI_DATA12/VIN1B_D2/GPMC_A10/SYS_NIRQ2/GPIO2_13) ; also on sheet 7
H_VIN1A_D11: U5000.K18(VIN1A_D11/CPI_DATA13/VIN1B_D3/GPMC_A11/SYS_NIRQ1/GPIO2_14) ; also on sheet 7
H_VIN1A_D12: U5000.K17(VIN1A_D12/CPI_DATA14/VIN1B_D4/GPMC_A12/DMA_EVT1/GPIO2_15) ; also on sheet 7
H_VIN1A_D13: U5000.K19(VIN1A_D13/CPI_WEn/VIN1B_D5/GPMC_A13/DMA_EVT2/GPIO2_16) ; also on sheet 7
H_VIN1A_D14: U5000.K20(VIN1A_D14/CPI_FID/VIN1B_D6/GPMC_A14/MCASP1_AXR14/GPIO2_17) ; also on sheet 7
H_VIN1A_D15: U5000.L21(VIN1A_D15/CPI_DATA15/VIN1B_D7/GPMC_A15/MCASP1_AXR15/GPIO2_18) ; also on sheet 7
H_VIN1A_DE0: U5000.F21(VIN1A_DE0/CPI_HSYNC/VIN1B_CLK1/CLKOUT1/GPIO1_31) ; also on sheet 7
H_VIN1A_FLD0: R9452.2 U5000.F20(VIN1A_FLD0/CPI_VSYNC/VIN2B_CLK1/CLKOUT2/GPIO2_0) ; also on sheet 7
H_VIN1A_HSYN0: U5000.F19(VIN1A_HSYNC0/CPI_DATA0/VIN1A_DE0/GPIO2_1) ; also on sheet 7
H_VIN1A_VSYN0: U5000.G19(VIN1A_VSYNC0/CPI_DATA1/GPIO2_2) ; also on sheet 7
H_VIN2A_CLK0: U5000.L22(VIN2A_CLK0/GPIO2_19) ; also on sheet 7
H_VIN2A_DE0: U5000.M17(VIN2A_DE0/CAM_STROBE/VIN2B_HSYNC1/VIN2B_DE1/GPIO4_21) ; also on sheet 7
H_VIN2A_FLD0: U5000.M18(VIN2A_FLD0/CAM_SHUTTER/VIN2B_VSYNC1/GPIO4_22) ; also on sheet 7
H_VOUT1_CLK: U5000.AB17(VOUT1_CLK/VIN1A_D12/CLKOUT0/VIN2A_CLK0/GPIO2_20) ; also on sheet 7
H_VOUT1_D0: U5000.W16(VOUT1_D0/MCASP1_AXR0/MMC_CLK/GPIO2_25) ; also on sheet 7
H_VOUT1_D1: U5000.V16(VOUT1_D1/MCASP1_AXR1/MMC_CMD/GPIO2_26) ; also on sheet 7
H_VOUT1_D2: U5000.U15(VOUT1_D2/MCASP1_AXR2/MCASP1_AXR8/MMC_DAT0/OBS0/OBS16/OBS_IRQ1/GPIO2_27) ; also on sheet 7
H_VOUT1_D3: U5000.V15(VOUT1_D3/MCASP1_AXR3/MCASP1_AXR9/MMC_DAT1/OBS1/OBS17/OBS_DMARQ1/GPIO2_28) ; also on sheet 7
H_VOUT1_D4: U5000.Y15(VOUT1_D4/MCASP1_AXR4/MCASP1_AXR10/MMC_DAT2/OBS2/OBS18/GPIO2_29) ; also on sheet 7
H_VOUT1_D5: U5000.W15(VOUT1_D5/MCASP1_AXR5/MCASP1_AXR11/MMC_DAT3/OBS3/OBS19/VIN2A_CLK0/GPIO2_30) ; also on sheet 7
H_VOUT1_D6: TP8157.1(TP) U5000.AA15(VOUT1_D6/MCASP1_AXR6/MCASP1_AXR12/ESM_ERROR/OBS4/OBS20/VIN2A_DE0/GPIO2_31) ; also on sheet 7
H_VOUT1_D7: U5000.AB15(VOUT1_D7/MCASP1_AXR7/eCAP1_IN_PWM1_OUT/MCASP1_AXR13/EMU3/VIN2A_FLD0/GPIO3_0) ; also on sheet 7
H_VOUT1_D8: U5000.AA14(VOUT1_D8/MCASP1_AXR8/VIN2A_D0/GPMC_A20/EMU4/GPIO3_1) ; also on sheet 7
H_VOUT1_D9: U5000.AB14(VOUT1_D9/MCASP1_AXR9/VIN2A_D1/GPMC_A21/EMU5/GPIO3_2) ; also on sheet 7
H_VOUT1_D10: U5000.U13(VOUT1_D10/MCASP1_AXR10/VIN2A_D2/GPMC_A22/EMU6/OBS5/OBS21/OBS_IRQ2/GPIO3_3) ; also on sheet 7
H_VOUT1_D11: U5000.V13(VOUT1_D11/MCASP1_AXR11/VIN2A_D3/GPMC_A23/EMU7/OBS6/OBS22/OBS_DMARQ2/GPIO3_4) ; also on sheet 7
H_VOUT1_D12: U5000.Y13(VOUT1_D12/MCASP1_AXR12/VIN2A_D4/GPMC_A24/EMU8/OBS7/OBS23/GPIO3_5) ; also on sheet 7
H_VOUT1_D13: U5000.W13(VOUT1_D13/MCASP1_AXR13/VIN2A_D5/GPMC_A25/EMU9/OBS8/OBS24/GPIO3_6) ; also on sheet 7
H_VOUT1_D14: U5000.U11(VOUT1_D14/MCASP1_AXR14/VIN2A_D6/GPMC_A26/EMU10/OBS9/OBS25/GPIO3_7) ; also on sheet 7
H_VOUT1_D15: U5000.V11(VOUT1_D15/MCASP1_AXR15/VIN2A_D7/GPMC_A27/EMU11/OBS10/OBS26/GPIO3_8) ; also on sheet 7
H_VOUT1_D16: U5000.U9(VOUT1_D16/MCASP1_AHCLKX/VIN2A_D8/GPMC_A0/MCASP1_ARX8/VIN2B_D0/EMU12/GPIO3_9) ; also on sheet 7
H_VOUT1_D17: U5000.W11(VOUT1_D17/VIN2A_D9/GPMC_A1/MCASP1_ARX9/VIN2B_D1/EMU13/GPIO3_10) ; also on sheet 7
H_VOUT1_D18: U5000.V9(VOUT1_D18/VIN2A_D10/GPMC_A2/MCASP1_AXR10/VIN2B_D2/EMU14/OBS11/OBS27/GPIO3_11) ; also on sheet 7
H_VOUT1_D19: U5000.W9(VOUT1_D19/VIN2A_D11/GPMC_A3/MCASP1_AXR11/VIN2B_D3/EMU15/OBS12/OBS28/GPIO3_12) ; also on sheet 7
H_VOUT1_D20: U5000.U8(VOUT1_D20/VIN2A_D12/GPMC_A4/MCASP1_AXR12/VIN2B_D4/EMU16/OBS13/OBS29/GPIO3_13) ; also on sheet 7
H_VOUT1_D21: U5000.W8(VOUT1_D21/VIN2A_D13/GPMC_A5/MCASP1_AXR13/VIN2B_D5/EMU17/OBS14/OBS30/GPIO3_14) ; also on sheet 7
H_VOUT1_D22: U5000.U7(VOUT1_D22/VIN2A_D14/GPMC_A6/MCASP1_AXR14/VIN2B_D6/EMU18/OBS15/OBS31/GPIO3_15) ; also on sheet 7
H_VOUT1_D23: U5000.V7(VOUT1_D23/VIN2A_D15/GPMC_A7/MCASP1_AXR15/VIN2B_D7/EMU19/GPIO3_16) ; also on sheet 7
H_VOUT1_DE: TP8155.1(TP) U5000.U17(VOUT1_DE/MCASP1_ACLKX/VIN1A_D13/CLKOUT1/GPIO2_21) ; also on sheet 7
H_VOUT1_FLD: TP8156.1(TP) U5000.W17(VOUT1_FLD/MCASP1_FSX/VIN1A_D14/CLKOUT2/GPIO2_22) ; also on sheet 7
H_VOUT1_HSYNC: U5000.AA17(VOUT1_HSYNC/MCASP1_ACLKR/VIN1A_D15/VIN2A_DE0/GPIO2_23) ; also on sheet 7
H_VOUT1_VSYNC: U5000.U16(VOUT1_VSYNC/MCASP1_FSR//VIN1A_D16/VIN2A_FLD0/GPIO2_24) ; also on sheet 7
H_XREF_CLK0: TP3005.1(TP) U5000.M1(XREF_CLK0/CLKOUT0/SPI3_CS0/SPI2_CS1/SPI1_CS0/SPI1_CS1/GPIO3_31) ; also on sheet 7
IFORCE: TP8031.1(TP) U5000.A2(IFORCE)
OSC0_OE: J76.1(OE) R9160.1
OSC0_XI: C6121.1 R9158.1 Y6102.2
OSC1_XI: C6123.1 R9157.1 Y6101.3
PLL1_PDIV3_20MHZ: R9490.2 U114.10(Y3)
PLL2_PDIV5_22p5792MHz: R9489.2 U114.8(Y5)
PORz: TP60.1(TP) U5000.G3(PORZ) ; also on sheet 13 26 27
RESETn: TP59.1(TP) U5000.G4(RESETn) ; also on sheet 13
RSTOUTn: R256.1 TP58.1(TP) U5000.F4(RSTOUTn) ; also on sheet 8 9 22 26
SOCK_OSC0_XI: J76.3(OUT) R9159.1
THERM_V: R9167.2 R9169.1 RT5.1
VCAP_VDDRAM_CORE1: C5103.1 U5000.N15(CAP_VDDRAM_CORE1)
VCAP_VDDRAM_CORE2: C5091.1 U5000.M15(CAP_VDDRAM_CORE2)
VCAP_VDDRAM_DSPEVE: C5095.1 U5000.M14(CAP_VDDRAM_DSPEVE)
VPO_1V8: C8069.2 C8250.1 J76.4(VCC) L15.2 R9160.2 ; also on sheet 15 37
VPP: C5081.1 Q6.S TP8064.1(TP) U5000.F6(VPP)
VPP_EN: Q6.G R474.2 ; also on sheet 31
VPRH_DV: R632.1 ; also on sheet 7 8 9 10 11 13 15 16 17 18 19 20 21 22 23 26 27 28 31 35 36
VREF_ADC: C5000.1 C5104.1 J6116.1(CENTER) R9166.2 R9167.1 U5000.P20(ADC_VREFP)
VSENSE: TP8032.1(TP) U5000.B1(VSENSE)
N27519143: J6107.1 R9169.2 R9408.2
N28096318: J6107.3 R9410.2
N28096321: J6107.5 R9411.2
N28096324: J6107.7 R9412.2
N28096327: J6107.9 R9413.2
N28096330: J6107.11 R9414.2
N28584335: J6117.1(CENTER) R9415.2
N28584344: J6118.1(CENTER) R9409.2
N30220060: C181.1 C423.1 C8249.1 L15.1 U114.3(VDD) U114.6(VDDOUT1) U114.9(VDDOUT2)
N30220150: C432.1 U114.1(XIN/CLK) Y8.3(C1)
N30220152: C431.1 U114.16(XOUT) Y8.1(Y1)
N30220246: TP40.1(TP) U114.14(S2/SCL)
N30220248: TP39.1(TP) U114.2(S0)
N30220250: TP41.1(TP) U114.15(S1/SDA)
N30220252: TP50.1(TP) U114.4(VCTR)

Not connected (* = marked no-connect by the designer): U114 7(Y4)* 11(Y2)* 13(Y1)*; U5000 1(SKT1) 2(SKT2) 3(SKT3) 4(SKT4) 5(SKT5) 6(SKT6)

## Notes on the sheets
sheet 1
- REV
- DATE
- NOTES
- A
- 05/07/2014
- PROTOTYPES
- B
- 06/04/2014
- BETA
- C1
- 10/24/2014
- BETA -  CLEANUP
- D
- 05/27/2016
- ES 2.0
- SH01 - TITLE PAGE
  SH02 - ECN LIST
  SH03 - MAPPING/NOTES
  SH04 - SOC 1
  SH05 - SOC 2
  SH06 - SOC POWER
  SH07 - DDR3
  SH08 - VISIBILITY
  SH09 - BOOT/JTAG
  SH10 - I2C EXPANDER
  SH11 - MUX A/B/C
  SH12 - MUX D/E/F/G
  SH13 - MUX H/J/K
  SH14 - SD CARD/EEPROM/TMP
  SH15 - MEM NONVOLATILE
  SH16 - USB FTDI UART
  SH17 - CAN/SAFETY MCU
  SH18 - ETHERNET
  SH19 - POWER TPS443351DAP
  SH20 - POWER PMIC
  SH21 - POWER MISC SWITCHES
  SH22 - POWER MONITORS
  SH23 - POWER BENCH/MONITORS
  SH24 - VOUT LCD CONNECTOR
  SH25 - VOUT HDMI OUTPUT
  SH26 - VOUT FPD LINK
  SH27 - VIN DS90UH926Q
  SH28 - VIN CAMERA 1
  SH29 - VIN CAMERA 2
  SH30 - VIN CSI2
  SH31 - VIN HDMI IN-1
  SH32 - VIN HDMI IN-2
  SH33 - VIN HDMI IN-3
  SH34 - CPLD VOUT-1
  SH35 - CPLD VIN-1
  SH36 - TOOL HPC
  SH37 - TOOL POWER MONITOR
- E
- 09/19/2016
- ES 2.0 - UPDATE
- E1
- 05/03/2017
- DOC UPDATE FOR RELEASE
- REVISION STATUS OF SHEETS
- REV
- SH
- REV
- SH
- REV
- SH
- REV
- SH
- REV
- SH
- REV
- SH
- REV
- C1
- B
- C1
- B
- B
- A
- E
- DWN
- DATE
- SH
- 31
- 32
- 33
- 34
- 35
- 36
- 37
- J.A.C.
- 05/27/2016
- CHK
- DATE
- REV
- E
- B
- A
- A
- A
- A
- A
- C1
- C1
- C1
- T.W.K.
- 05/27/2016
- SH
- 21
- 22
- 23
- 24
- 25
- 26
- 27
- 28
- 29
- 30
- ENGR
- J.A.C.
- 05/27/2016
- DATE
- ENGR-MGR
- DATE
- REV
- A
- A
- B
- D
- D
- A
- B
- A
- D
- D
- J.A.C.
- 05/27/2016
- QA
- DATE
- SH
- 11
- 12
- 13
- 14
- 15
- 16
- 17
- 18
- 19
- 20
- C.M.D.
- 05/27/2016
- MFG
- DATE
- REV
- E1
- E
- B
- C1
- D
- D
- E
- D
- D
- E1
- NEXT ASSY
- USED ON
- RLSE
- J.A.C.
- 05/27/2016
- DATE
- SH
- 1
- 2
- 3
- 4
- 5
- 6
- 7
- 8
- 9
- 10
- APPLICATION
- J.A.C.
- 05/27/2016
sheet 3
- ER31
sheet 4
- Note:  Option for on-board/external VREF
- Note: Alternate Source/Visibility for ADC_IN0
- Silkscreen: ADC_INPUT
- Nominal: 100K
- Silkscreen:
  ADC0
- RSET( 4.7K, 6.8K,10K)
- Note: Single point contact at SOC.
- VFB0(0,2.7K)
- TVOUT(0,OPEN)
- ER24
- Note: Alternate Source/Visibility for OSC0
- Silkscreen: SOCKET_OSC0
- Silkscreen: OSC0
- ER25
- Note: CPU Test Points
- CLKOUT2
- Silkscreen: CPU_RESETN
- Note: Alternate Source/Visibility for OSC1
- Silkscreen: CPU_PORZ
- Silkscreen: OSC1
- Silkscreen: CPU_RSTOUTN
- Silkscreen: XREF_CLK0
- ER46
sheet 5
- Note:  See Data Manual/PCB Guidelines for VDD decoupling requirements.
- Note:  See Data Manual/PCB Guidelines for DSPEVE decoupling requirements.
- Note:  See Data Manual/PCB Guidelines for
  VDDS18V decoupling requirements.
- Note:  See Data Manual/PCB Guidelines for VDDSHVx decoupling requirements.
- Note:  These caps feed the VDDS supplies before
  the resistor breakout.
- Note:  EMIF Power Connections
  (Decoupling bottom of page)
- Note:  See Data Manual/PCB Guidelines for
  VCAP capacitor requirements.
- ER43
- Note:  See Data Manual/PCB Guidelines for DDR VDDS/VDDS18V decoupling  requirements.
